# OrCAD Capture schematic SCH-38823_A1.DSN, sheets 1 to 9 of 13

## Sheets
1 Page11 BOOT_CFG: size C; title: X-8MNANOLPD4-CPU; rev: A; company: NXP Semiconductor; note: SCH-38823 PDF: SPF-38823; note: NO. 192 Liangjing Rd. Pudong New Area, ShangHai
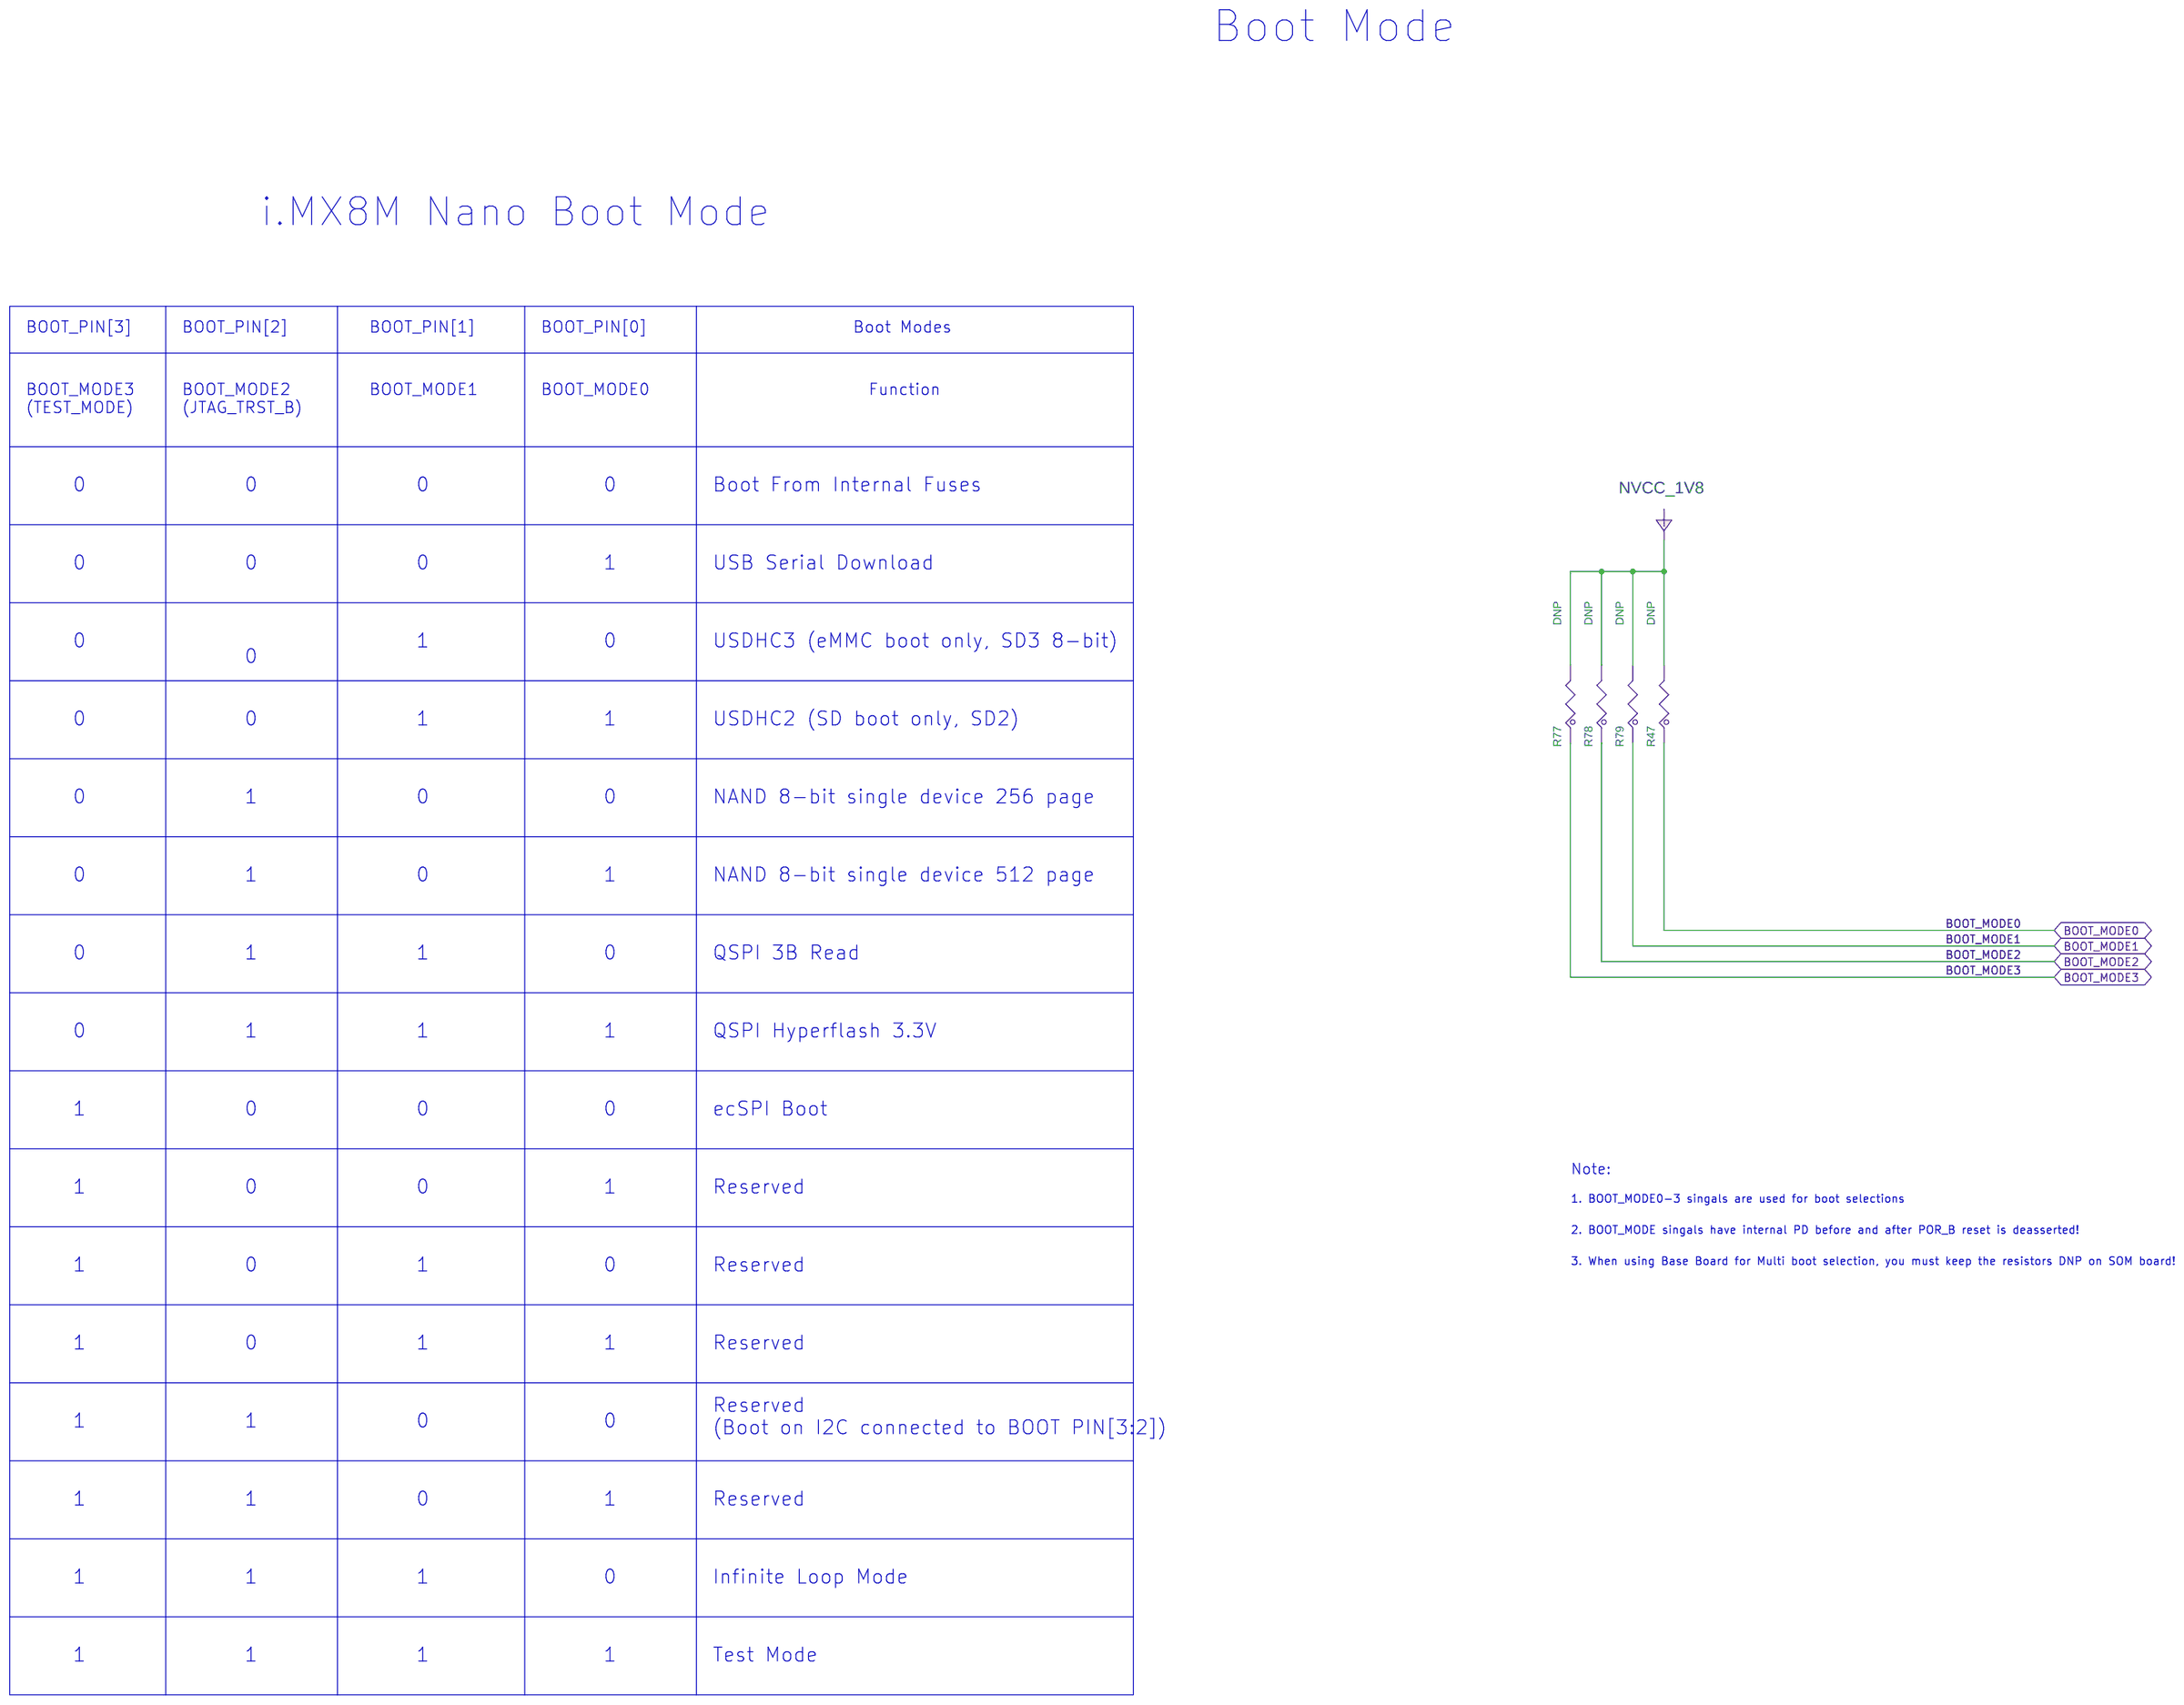
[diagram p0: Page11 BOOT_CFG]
2 Page01 COVER
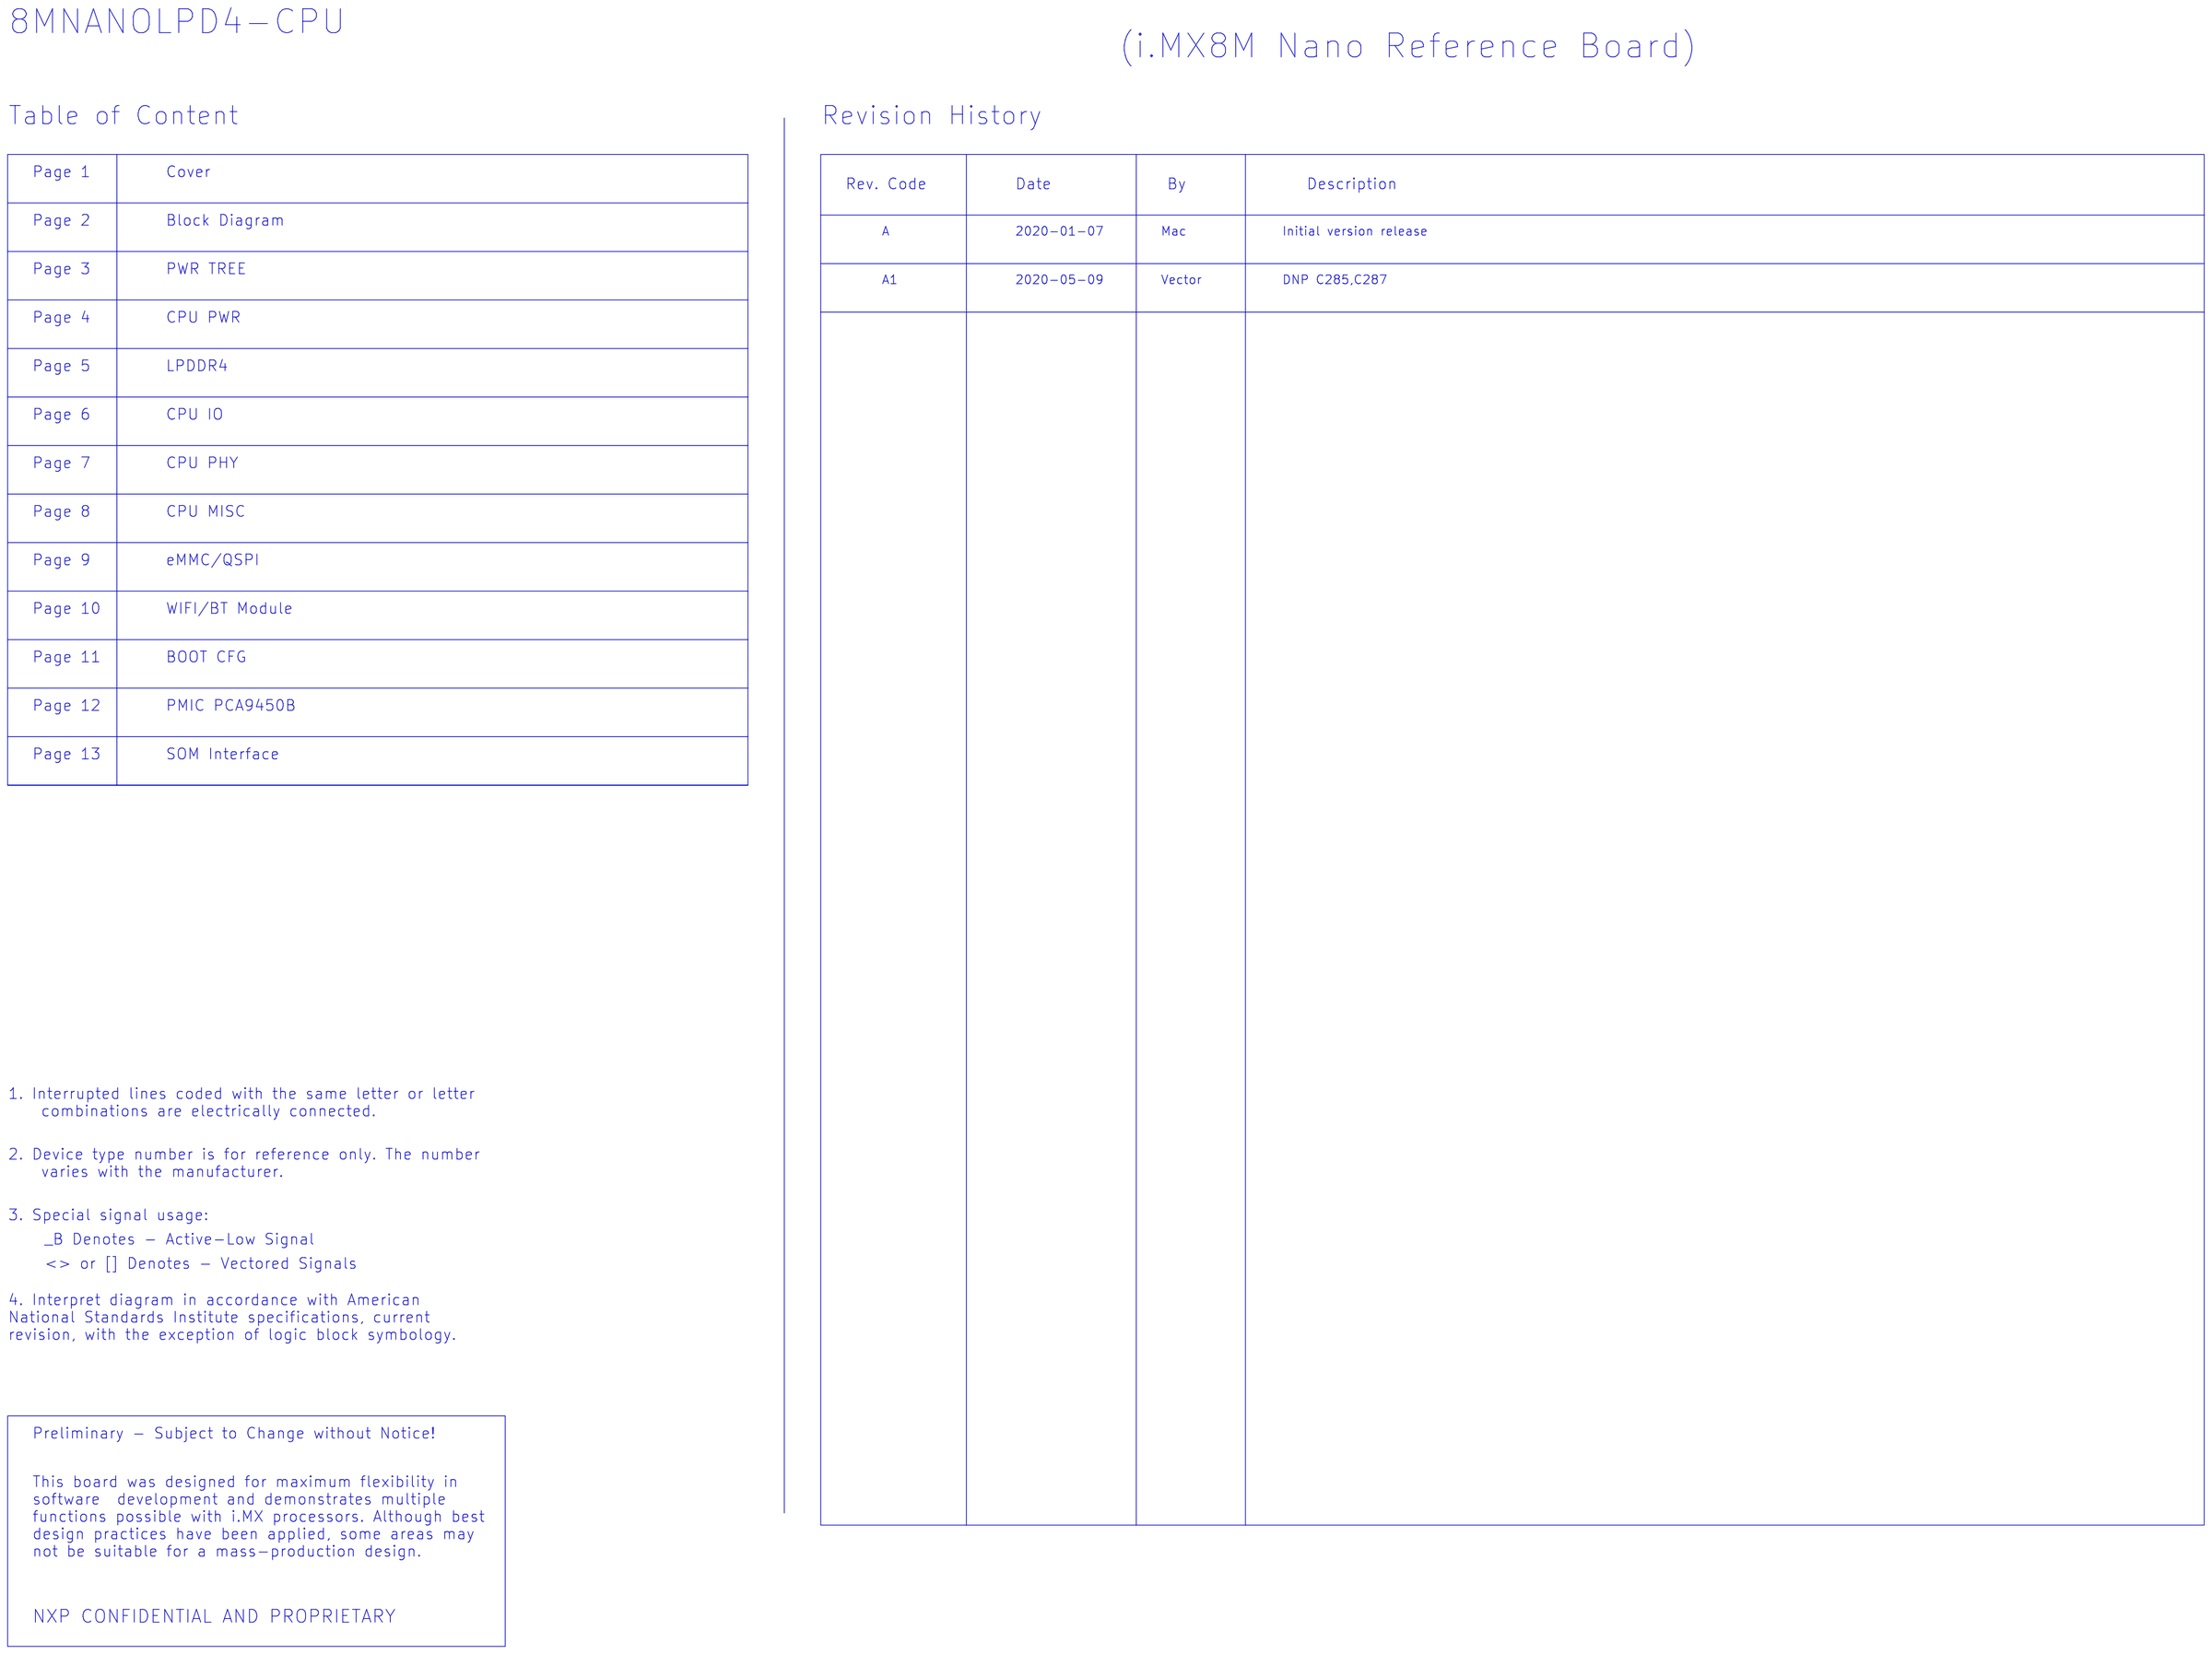
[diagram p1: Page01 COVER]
3 Page02 BLOCK DIAGRAM
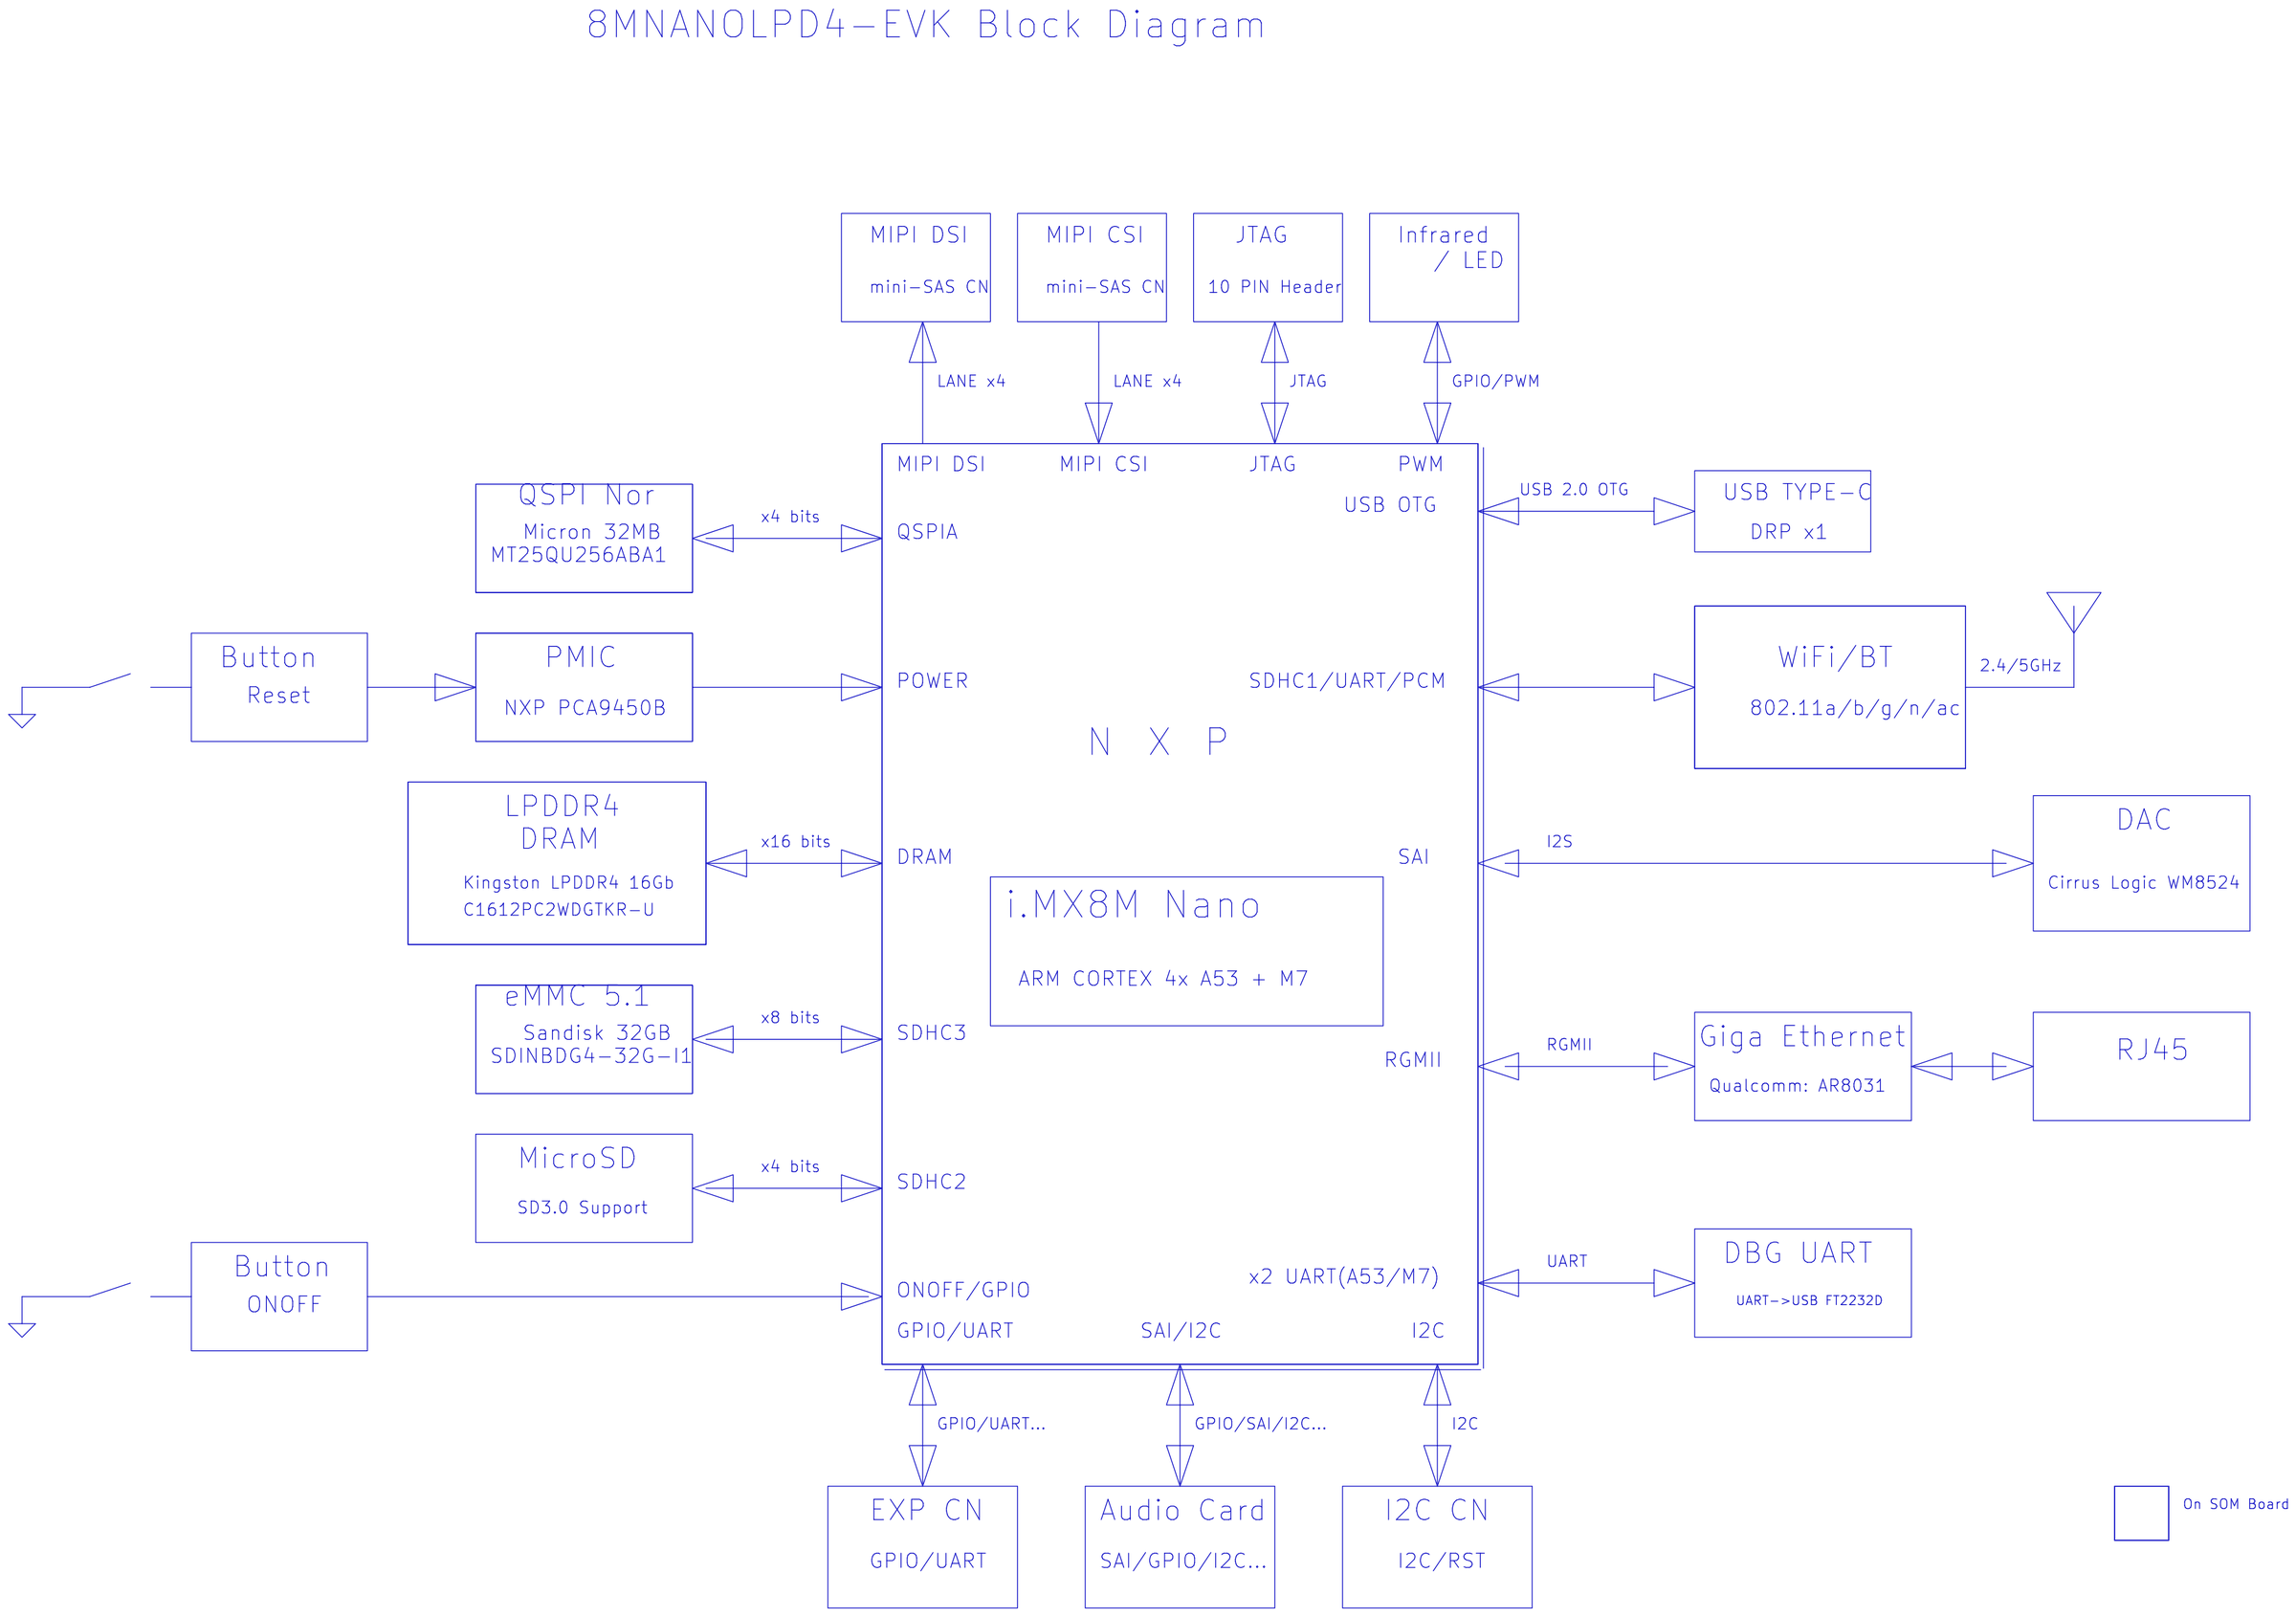
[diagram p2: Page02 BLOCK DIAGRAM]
4 Page03 PWR TREE
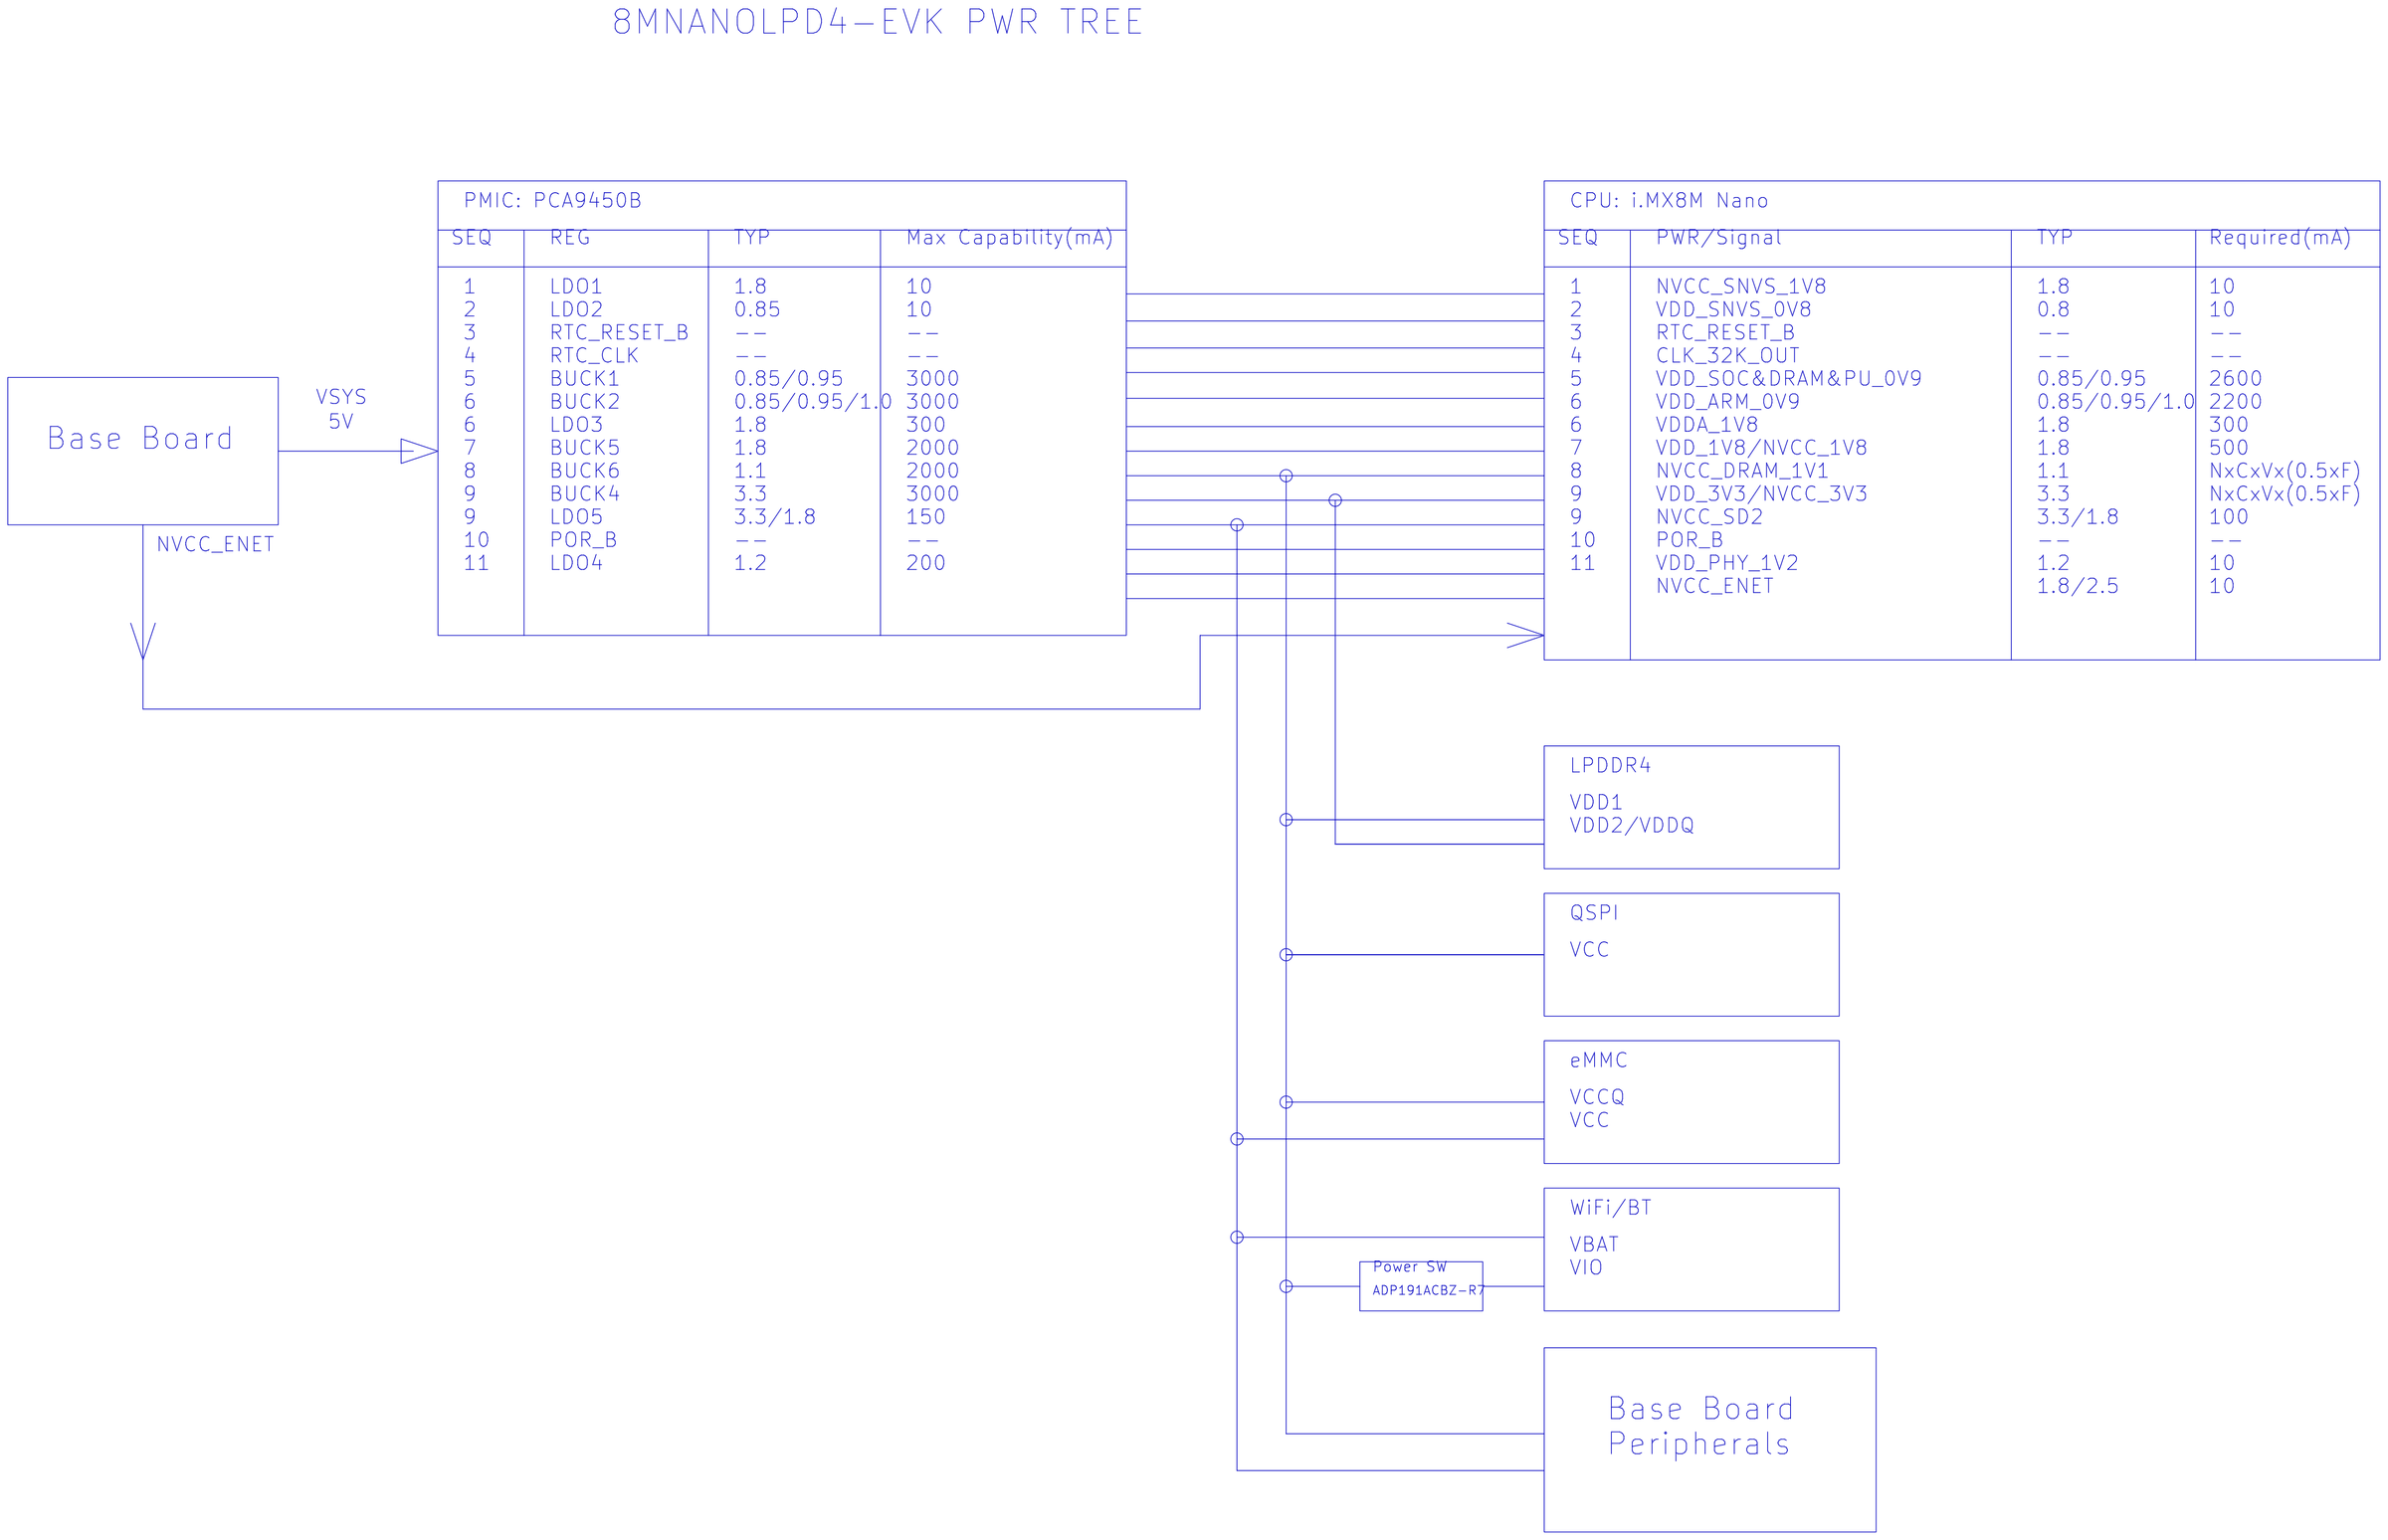
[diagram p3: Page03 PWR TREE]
5 Page04 CPU PWR: size C
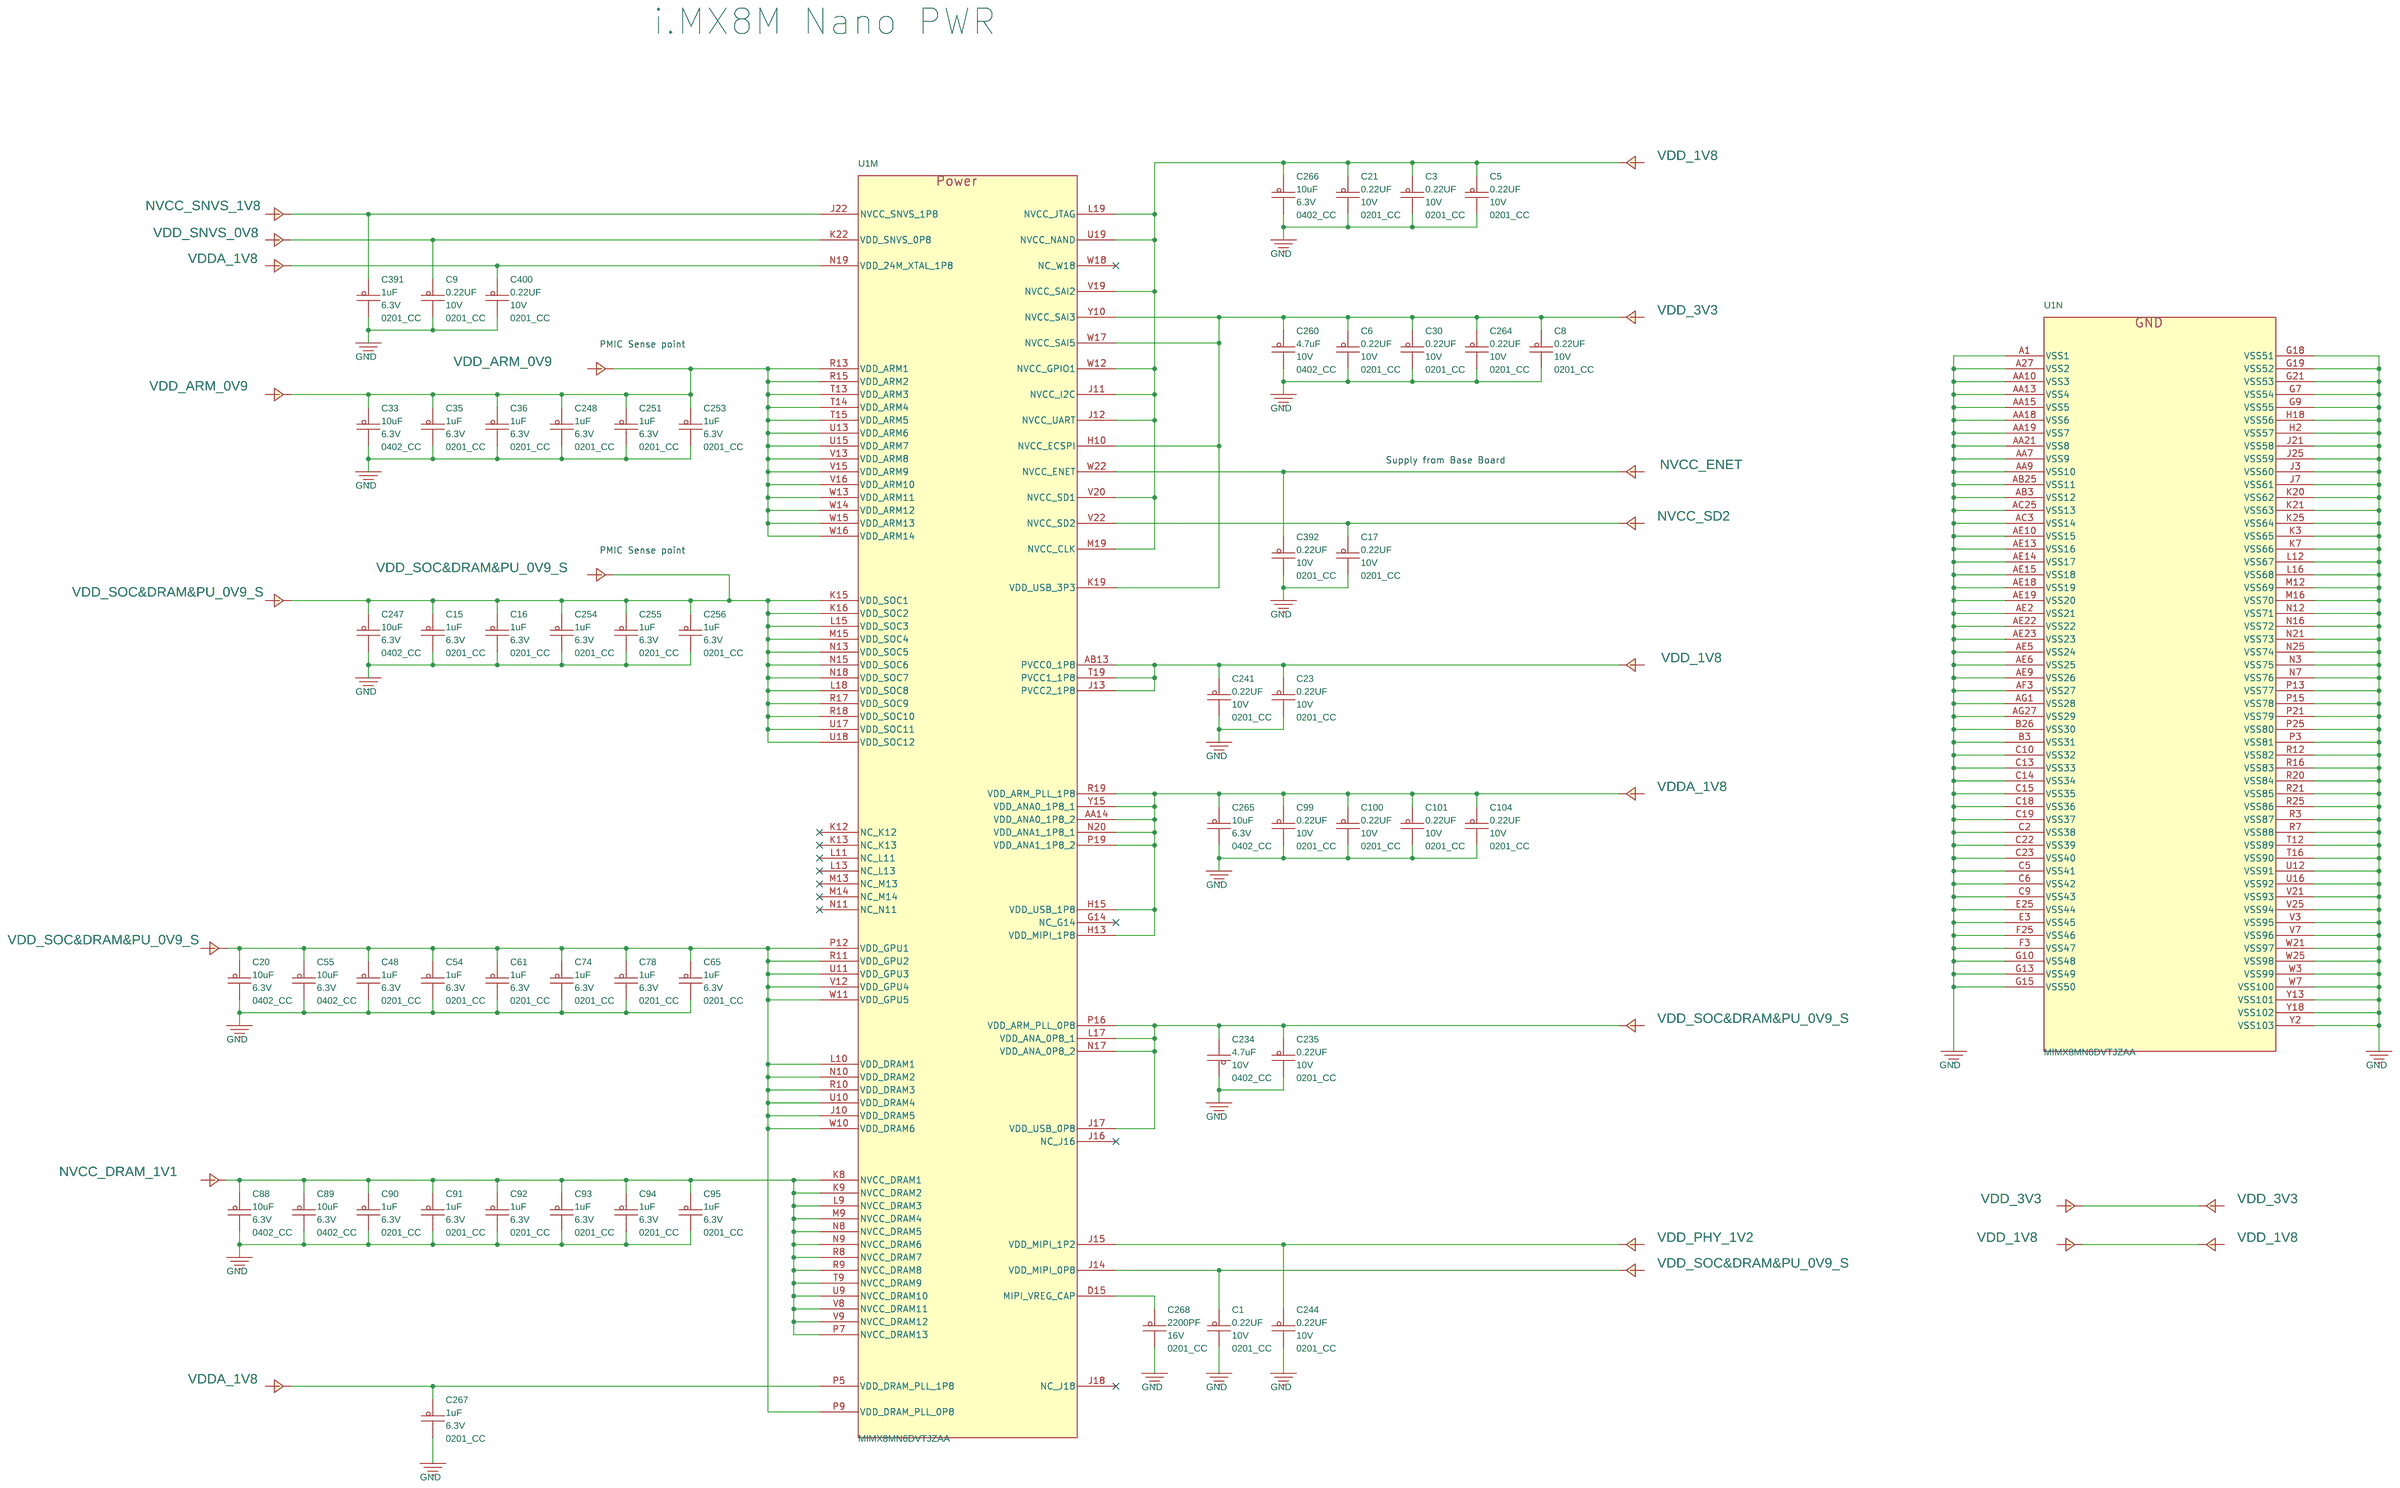
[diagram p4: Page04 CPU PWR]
6 Page05 LPDDR4: size C; title: X-8MNANOD4-CPU
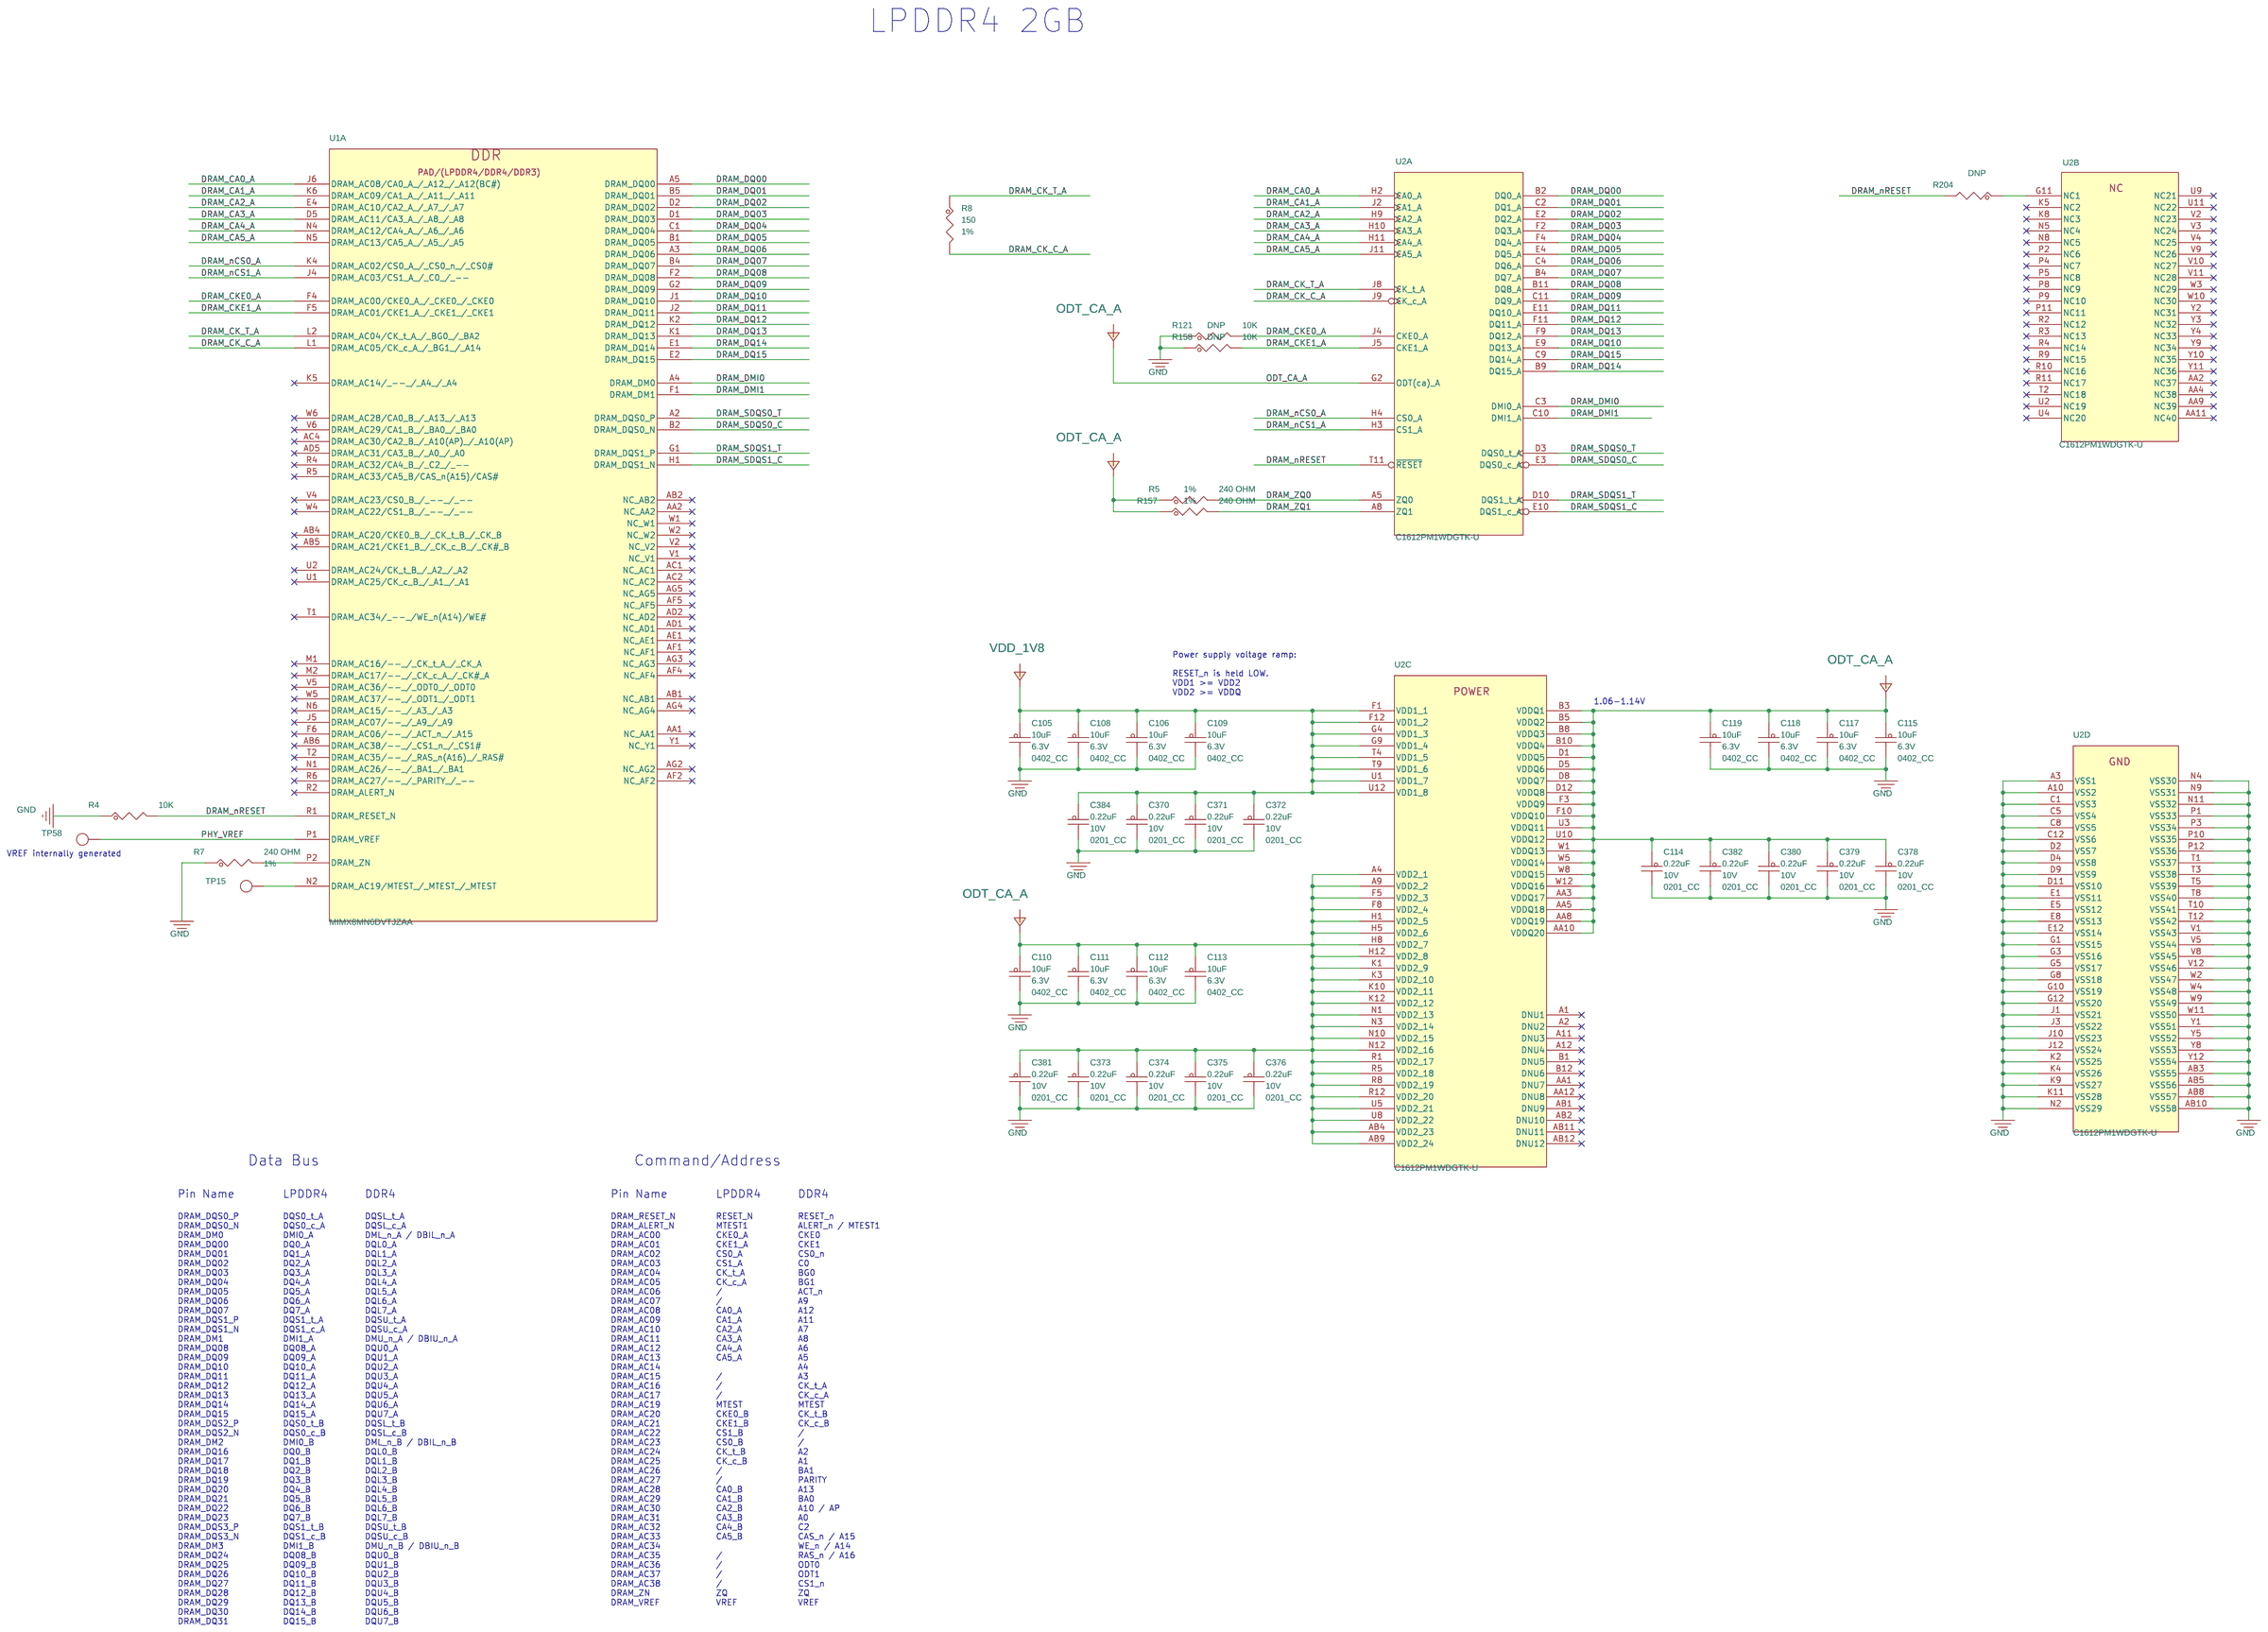
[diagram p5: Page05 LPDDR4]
7 Page06 CPU IO: size C; title: X-8MNANOD4-CPU
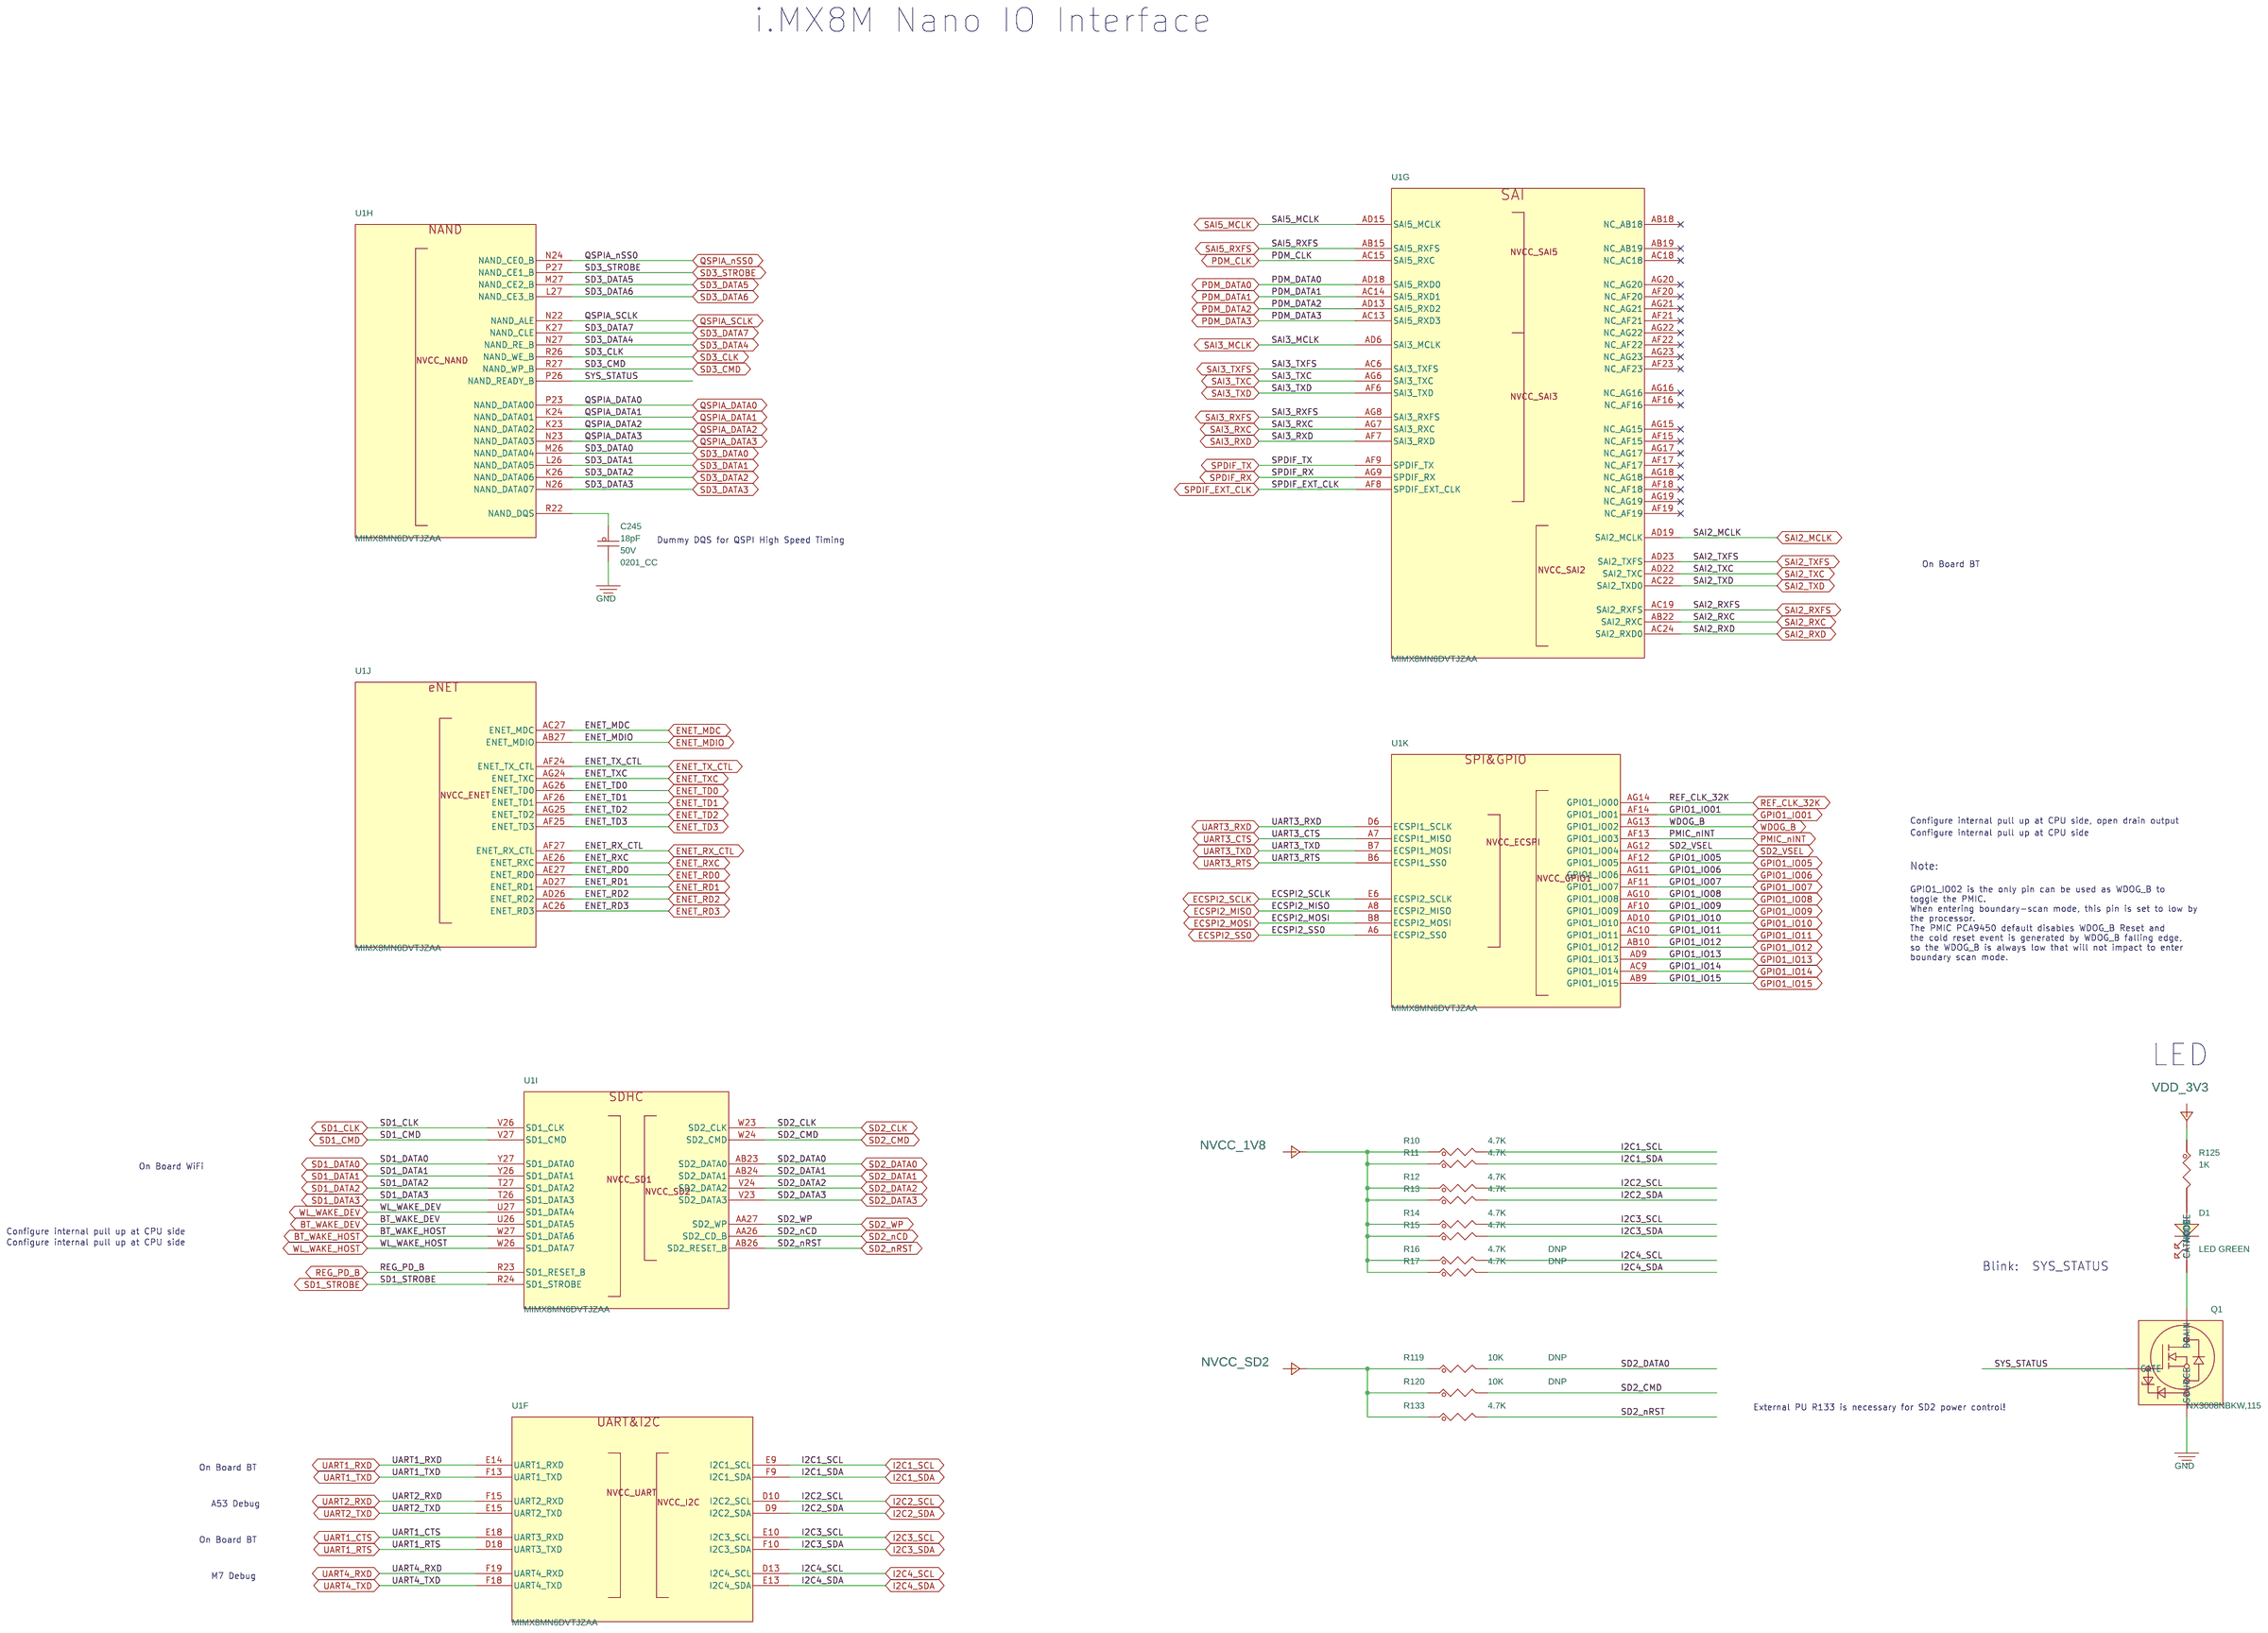
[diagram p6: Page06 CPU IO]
8 Page08 CPU MISC: size A4
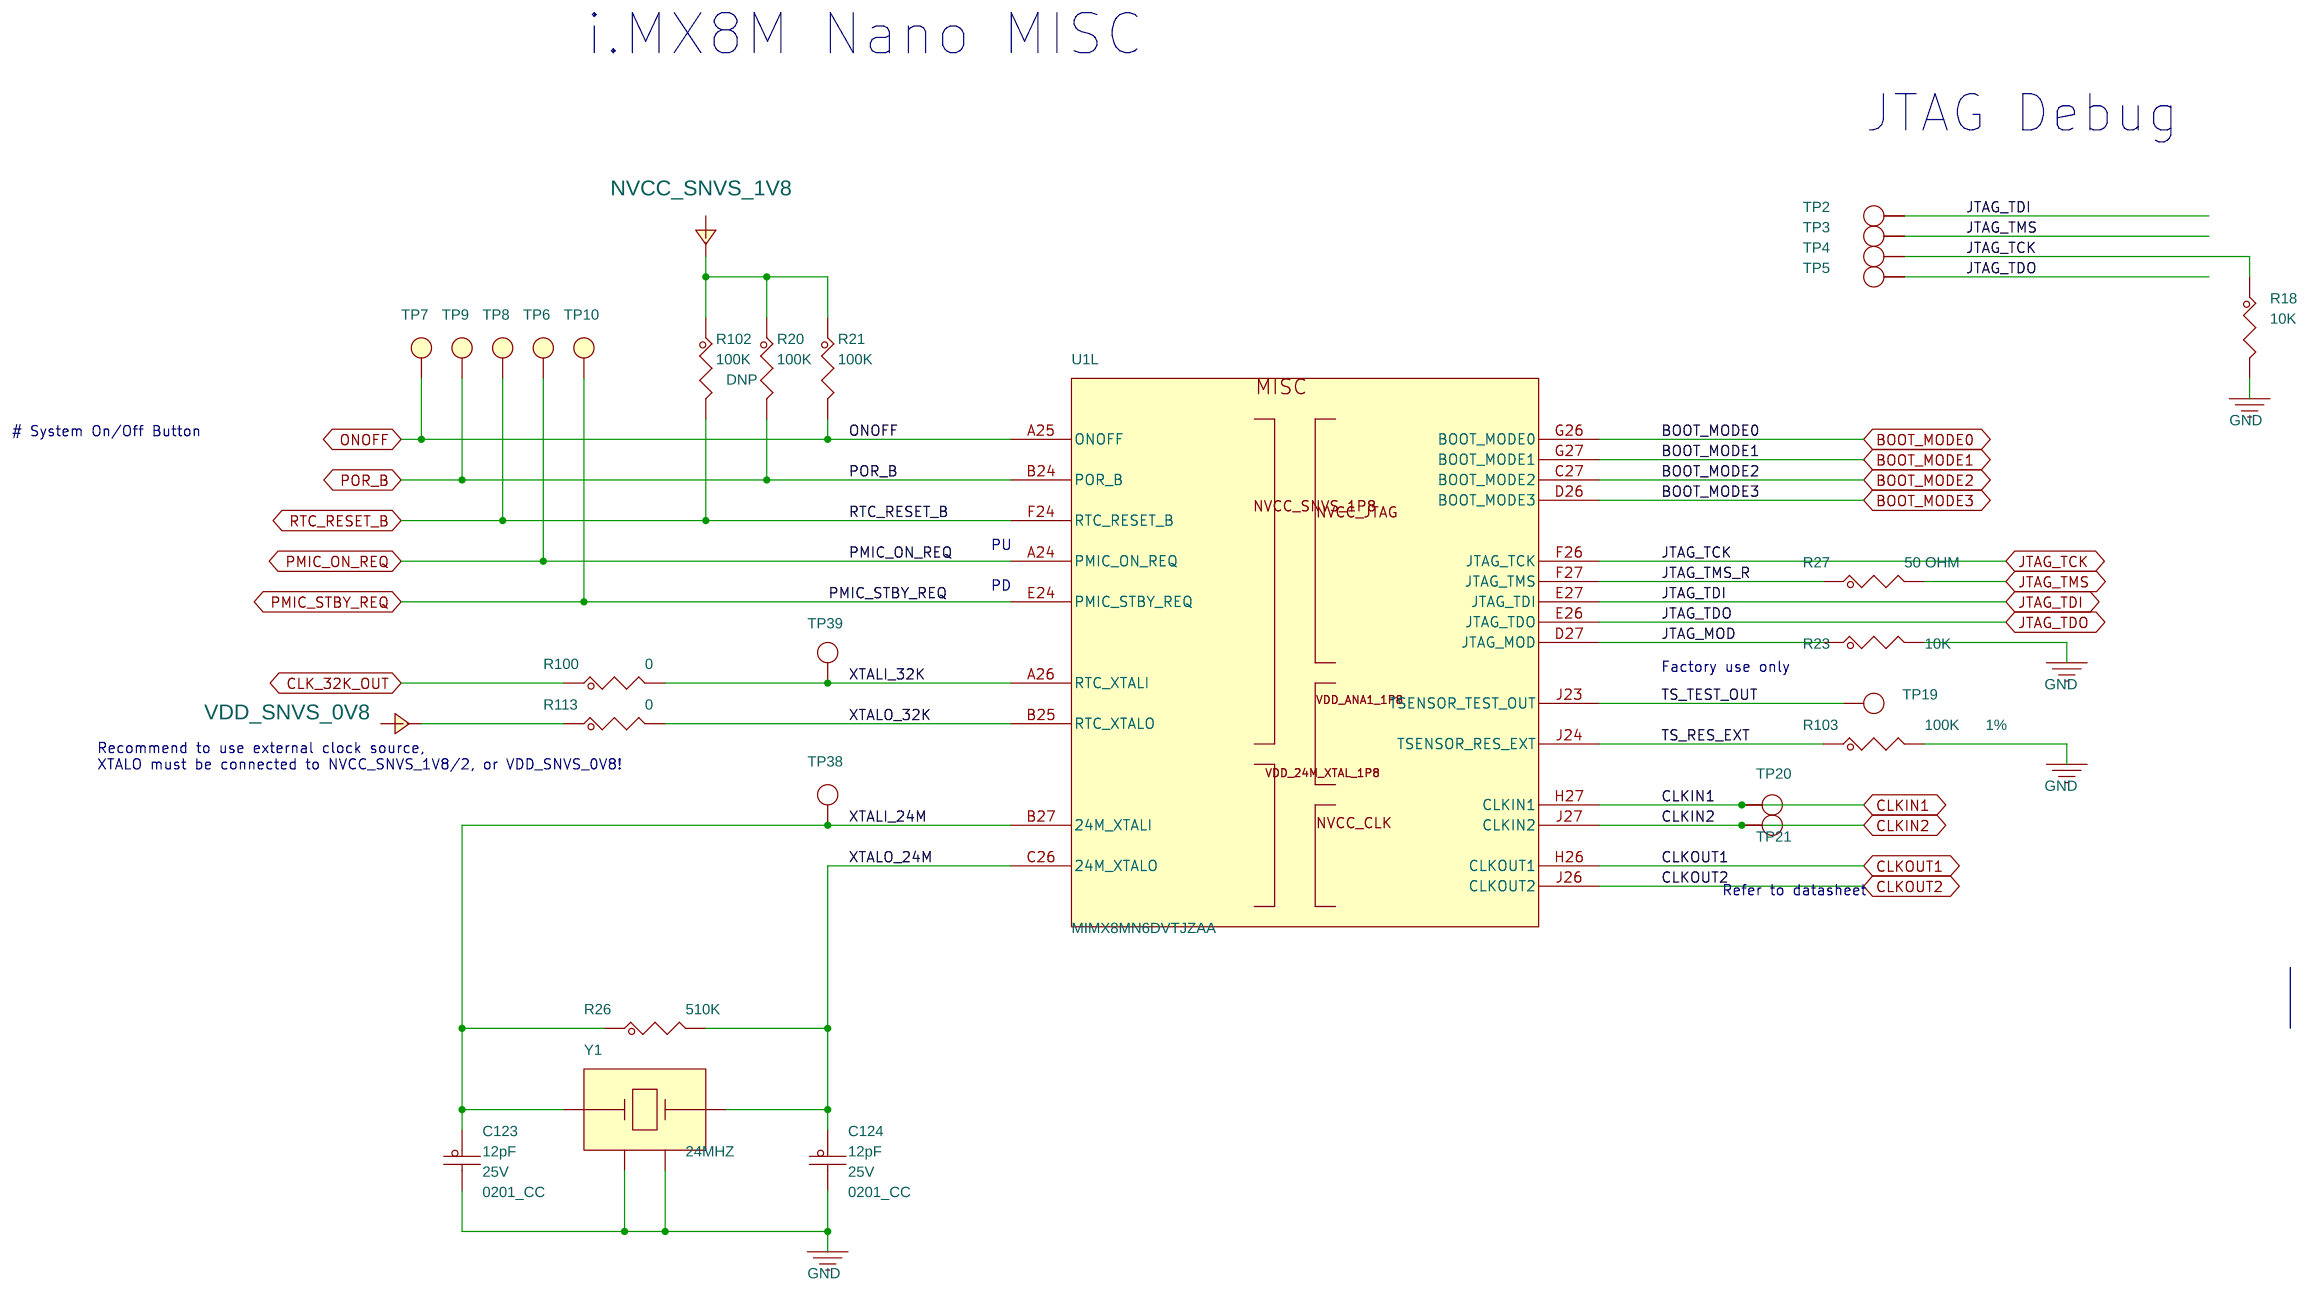
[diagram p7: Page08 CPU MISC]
9 Page07 CPU PHY: size B
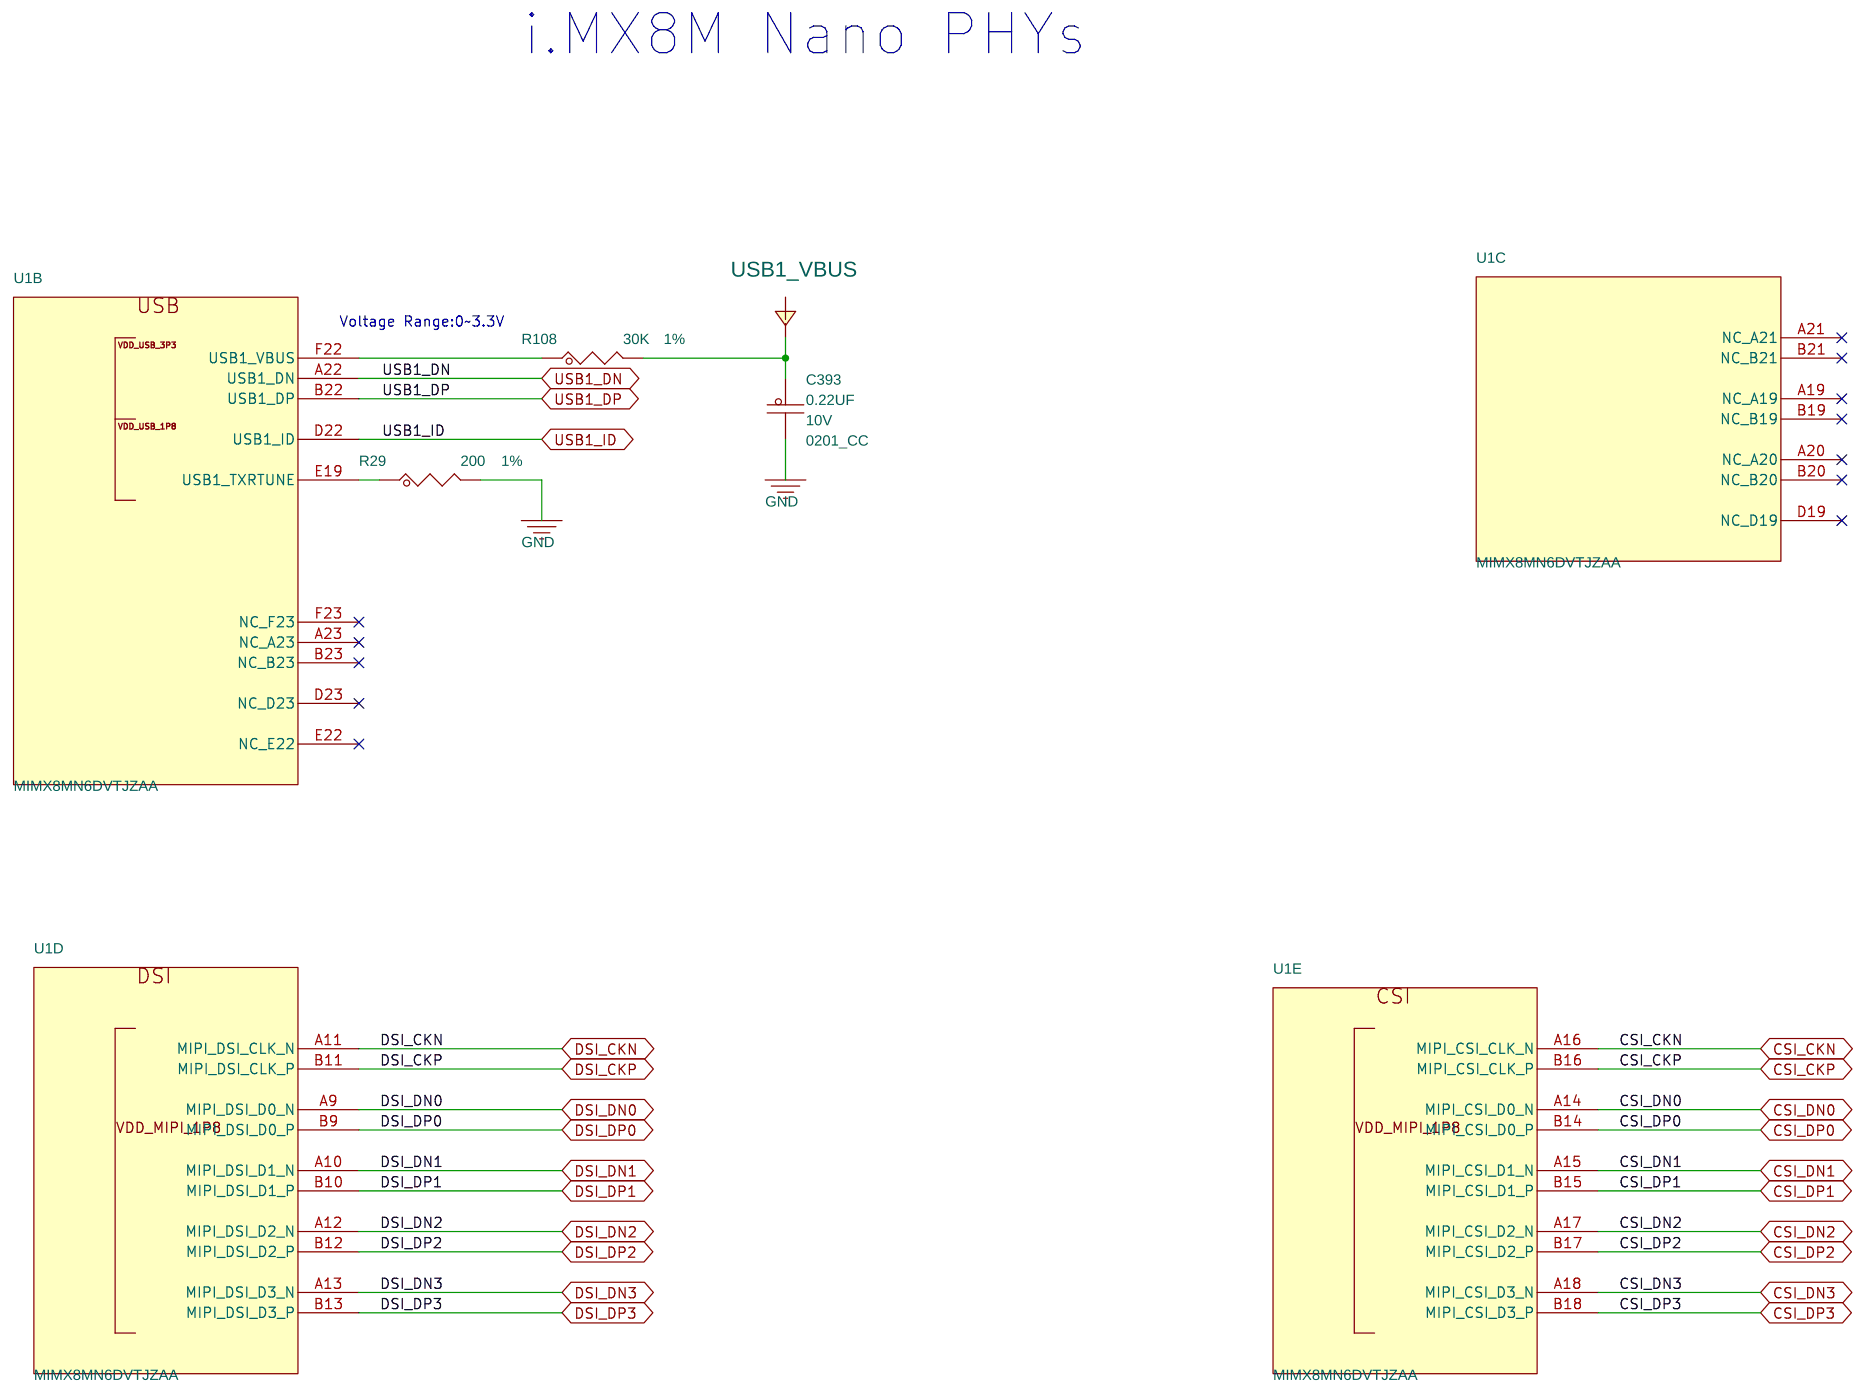
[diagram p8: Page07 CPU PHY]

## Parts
sheet Page04 CPU PWR
C1  0.22UF  [0201_CC]
C3  0.22UF  [0201_CC]
C5  0.22UF  [0201_CC]
C6  0.22UF  [0201_CC]
C8  0.22UF  [0201_CC]
C9  0.22UF  [0201_CC]
C15  1uF  [0201_CC]
C16  1uF  [0201_CC]
C17  0.22UF  [0201_CC]
C20  10uF  [0402_CC]
C21  0.22UF  [0201_CC]
C23  0.22UF  [0201_CC]
C30  0.22UF  [0201_CC]
C33  10uF  [0402_CC]
C35  1uF  [0201_CC]
C36  1uF  [0201_CC]
C48  1uF  [0201_CC]
C54  1uF  [0201_CC]
C55  10uF  [0402_CC]
C61  1uF  [0201_CC]
C65  1uF  [0201_CC]
C74  1uF  [0201_CC]
C78  1uF  [0201_CC]
C88  10uF  [0402_CC]
C89  10uF  [0402_CC]
C90  1uF  [0201_CC]
C91  1uF  [0201_CC]
C92  1uF  [0201_CC]
C93  1uF  [0201_CC]
C94  1uF  [0201_CC]
C95  1uF  [0201_CC]
C99  0.22UF  [0201_CC]
C100  0.22UF  [0201_CC]
C101  0.22UF  [0201_CC]
C104  0.22UF  [0201_CC]
C234  4.7uF  [0402_CC]
C235  0.22UF  [0201_CC]
C241  0.22UF  [0201_CC]
C244  0.22UF  [0201_CC]
C247  10uF  [0402_CC]
C248  1uF  [0201_CC]
C251  1uF  [0201_CC]
C253  1uF  [0201_CC]
C254  1uF  [0201_CC]
C255  1uF  [0201_CC]
C256  1uF  [0201_CC]
C260  4.7uF  [0402_CC]
C264  0.22UF  [0201_CC]
C265  10uF  [0402_CC]
C266  10uF  [0402_CC]
C267  1uF  [0201_CC]
C268  2200PF  [0201_CC]
C391  1uF  [0201_CC]
C392  0.22UF  [0201_CC]
C400  0.22UF  [0201_CC]
sheet Page05 LPDDR4
C105  10uF  [0402_CC]
C106  10uF  [0402_CC]
C108  10uF  [0402_CC]
C109  10uF  [0402_CC]
C110  10uF  [0402_CC]
C111  10uF  [0402_CC]
C112  10uF  [0402_CC]
C113  10uF  [0402_CC]
C114  0.22uF  [0201_CC]
C115  10uF  [0402_CC]
C117  10uF  [0402_CC]
C118  10uF  [0402_CC]
C119  10uF  [0402_CC]
C370  0.22uF  [0201_CC]
C371  0.22uF  [0201_CC]
C372  0.22uF  [0201_CC]
C373  0.22uF  [0201_CC]
C374  0.22uF  [0201_CC]
C375  0.22uF  [0201_CC]
C376  0.22uF  [0201_CC]
C378  0.22uF  [0201_CC]
C379  0.22uF  [0201_CC]
C380  0.22uF  [0201_CC]
C381  0.22uF  [0201_CC]
C382  0.22uF  [0201_CC]
C384  0.22uF  [0201_CC]
R4  10K  [0201_CC]
R5  240 OHM  [0201_CC]
R7  240 OHM  [0201_CC]
R8  150  [0402_CC]
R121  10K  [0201_CC]
R157  240 OHM  [0201_CC]
R158  10K  [0201_CC]
R204  0  [0402_CC]
TP15  TPAD_020  [tpad_020]
TP58  TPAD_020  [tpad_020]
U2  C1612PM1WDGTK-U  [bga200_0p65x0p8_10p1x14p6]  (sections A,B,C,D)
sheet Page06 CPU IO
C245  18pF  [0201_CC]
D1  LED GREEN  [LED_0603]
Q1  NX3008NBKW,115  [sc70_3]
R10  4.7K  [0201_CC]
R11  4.7K  [0201_CC]
R12  4.7K  [0201_CC]
R13  4.7K  [0201_CC]
R14  4.7K  [0201_CC]
R15  4.7K  [0201_CC]
R16  4.7K  [0201_CC]
R17  4.7K  [0201_CC]
R119  10K  [0201_CC]
R120  10K  [0201_CC]
R125  1K  [0201_CC]
R133  4.7K  [0201_CC]
sheet Page07 CPU PHY
C393  0.22UF  [0201_CC]
R29  200  [0201_CC]
R108  30K  [0201_CC]
sheet Page08 CPU MISC
C123  12pF  [0201_CC]
C124  12pF  [0201_CC]
R18  10K  [0201_CC]
R20  100K  [0201_CC]
R21  100K  [0201_CC]
R23  10K  [0201_CC]
R26  510K  [0402_CC]
R27  50 OHM  [0402_CC]
R100  0  [0402_CC]
R102  100K  [0201_CC]
R103  100K  [0201_CC]
R113  0  [0402_CC]
TP2  TPAD_020  [tpad_020]
TP3  TPAD_020  [tpad_020]
TP4  TPAD_020  [tpad_020]
TP5  TPAD_020  [tpad_020]
TP6  TP_35MIL  [testpoint_35mil]
TP7  TP_35MIL  [testpoint_35mil]
TP8  TP_35MIL  [testpoint_35mil]
TP9  TP_35MIL  [testpoint_35mil]
TP10  TP_35MIL  [testpoint_35mil]
TP19  TPAD_020  [tpad_020]
TP20  TPAD_020  [tpad_020]
TP21  TPAD_020  [tpad_020]
TP38  TPAD_020  [tpad_020]
TP39  TPAD_020  [tpad_020]
U1  MIMX8MN6DVTJZAA  [bga486_0p5_14x14]  (sections A,B,C,D,E,F,G,H,I,J,K,L,M,N)
Y1  24MHZ  [xtlosc4_3p2x2p5mm_sm]
sheet Page11 BOOT_CFG
R47  10K  [0402_CC]
R77  10K  [0402_CC]
R78  10K  [0402_CC]
R79  10K  [0402_CC]

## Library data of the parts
C1 C244 = CAP_NP: CAP CER 0.22UF 10V 20% X5R 0201; AGILE_PN: 150-78815; CAD_APPROVED: Yes; FPLIST: CC0201,CC0201_HD,0201_CC,CC_0201_CIR,0201_CC_012SM_NSP; HEIGHT: 0.33MM; MFG_NAME01: Taiyo Yuden; MFG_PN01: LMK063BJ224MP-F; ROHS: Yes; Tolerance: 20%; VOLTAGE: 10V
C3 C5 C6 C8 C9 C17 C21 C23 C99-C101 C104 C114 C235 C241 C264 C370-C376 C378-C382 C384 C392 C393 C400 = CAP_NP: CAP CER 0.22UF 10V 20% X5R 0201; AGILE_PN: 150-78815; CAD_APPROVED: Yes; FPLIST: CC0201,CC0201_HD,0201_CC; HEIGHT: 0.33MM; MFG_NAME01: Taiyo Yuden; MFG_PN01: LMK063BJ224MP-F; ROHS: Yes; Tolerance: 20%; VOLTAGE: 10V
C15 C16 C35 C36 C48 C54 C61 C65 C74 C78 C90-C95 C248 C251 C253-C256 C267 C391 = CAP_NP: CAP CER 1uF 6.3V 20% X5R 0201; AGILE_PN: 150-79407; CAD_APPROVED: Yes; FPLIST: CC0201,CC0201_HD,0201_CC,0201_CC_012SM_NSP; HEIGHT: 0.35MM; MFG_NAME01: AVX; MFG_PN01: 02016D105MAT2A; Package Size: 0201; Package Type: 7” reel; ROHS: Yes; Tolerance: 20%; VOLTAGE: 6.3V
C20 C33 C55 C88 C89 C105 C106 C108-C113 C115 C117-C119 C247 C265 C266 = CAP_NP: CAP CER 10UF 6.3V 20% X5R 0402; AGILE_PN: 150-79163; CAD_APPROVED: Yes; FPLIST: CC0402_25,CC0402_HD,0402_CC; HEIGHT: 0.65 MM; MFG_NAME01: SAMSUNG ELECTRO MECHANICS; MFG_PN01: CL05A106MQ5NUNC; ROHS: Yes; Tolerance: 20%; VOLTAGE: 6.3V
C30 = CAP_NP: CAP CER 0.22UF 10V 20% X5R 0201; AGILE_PN: 150-78815; CAD_APPROVED: Yes; FPLIST: CC0201,CC0201_HD,0201_CC,0201_CC_012SM_NSP; HEIGHT: 0.33MM; MFG_NAME01: Taiyo Yuden; MFG_PN01: LMK063BJ224MP-F; ROHS: Yes; Tolerance: 20%; VOLTAGE: 10V
C234 C260 = CAP_NP: CAP CER 4.7uF 10V 10% X5R 0402; AGILE_PN: 150-80044; CAD_APPROVED: Yes; FPLIST: CC0402_25,CC0402_HD,0402_CC; HEIGHT: 0.65MM; MFG_NAME01: Samsung Electro Mechanics; MFG_PN01: CL05A475KP5NRNC; ROHS: Yes; Tolerance: 10%; VOLTAGE: 10V
C268 = CAP_NP: CAP CER 2200PF 16V 10% X7R 0201; AGILE_PN: 150-78660; CAD_APPROVED: Yes; FPLIST: CC0201,CC0201_HD,0201_CC; HEIGHT: 0.33 MM; MFG_NAME01: MURATA; MFG_PN01: GRM033R71C222KA88D; ROHS: Yes; Tolerance: 20%; VOLTAGE: 16V
R4 R18 R23 = RES: RES MF 10K 1/20W 5% 0201; AGILE_PN: 470-79719; CAD_APPROVED: Yes; FPLIST: RC0201,0201_CC; HEIGHT: 0.26 MM; MFG_NAME01: RALEC ELECTRONIC CORP; MFG_PN01: RTT01103JTH; ROHS: Yes; Tolerance: 5%
R5 R7 R157 = RES: RES MF 240 OHM 1/20W 1% 0201; AGILE_PN: 470-81317; CAD_APPROVED: Yes; FPLIST: CC0201,CC0201_HD,0201_CC; HEIGHT: 0.26MM; MFG_NAME01: YAGEO AMERICA; MFG_PN01: RC0201FR-07240RL; ROHS: Yes; Temp Range: -55°C ~ 125°C; Temp_Range: -55°C ~ 125°C; Tolerance: 1%; VOLTAGE: 25V
R8 = RES: RES MF 150 OHM 1/16W 1% 0402; AGILE_PN: 470-75353; CAD_APPROVED: Yes; FPLIST: RC0402_25,RC0402_HD,0402_CC; HEIGHT: 0.4MM; MFG_NAME01: NIC COMPONENTS CORP; MFG_PN01: NRCL04F1500TRF; ROHS: Yes; Tolerance: 1%
R119-R121 R158 = RES: RES MF 10K 1/20W 5% 0201; AGILE_PN: 470-79719; ASSY_OPT: DNP; CAD_APPROVED: Yes; FPLIST: RC0201,0201_CC; HEIGHT: 0.26 MM; MFG_NAME01: RALEC ELECTRONIC CORP; MFG_PN01: RTT01103JTH; ROHS: Yes; Tolerance: 5%
R204 = RES: RES MF ZERO OHM 1/16W 5% 0402; AGILE_PN: 470-75394; ASSY_OPT: DNP; CAD_APPROVED: Yes; FPLIST: RC0402_25,RC0402_HD,RC0402_X2,0402_CC; HEIGHT: 0.45 MM; MFG_NAME01: YAGEO AMERICA; MFG_PN01: RC0402JR-070RL; ROHS: Yes; SIGNAL_MODEL: DEFAULT_RESISTOR_10000OHM_2_1; TOL: 1%; Tolerance: 5%; VOLTAGE: 1/16W
TP2-TP5 TP15 TP19-TP21 TP38 TP39 TP58 = TESTLOOP: TEST POINT PAD 0.5MM DIA SMT, NO PART TO ORDER; AGILE_PN: 211-77484; ASSY_OPT: DNP; CAD_APPROVED: Yes; HEIGHT: 0.1MM; ROHS: Yes
U2 = C1612PC2WDGTKR-U_BGA200P: IC MEM LPDDR4 SDRAM 1024 Meg x 16 1.1V FBGA200; AGILE_PN: TMP-WF-36533; CAD_APPROVED: Yes; HEIGHT: 1.0MM; MFG_NAME01: KINGSTON TECHNOLOGY CORP; PRE_APN: 334-77858; ROHS: Yes; Temp Range: -10C to +85C; Temp_Range: -10C to +85C; VOLTAGE: 1.1V
C245 = CAP_NP: CAP CER 18pF 50V 5% C0G 0201; AGILE_PN: 150-79476; CAD_APPROVED: Yes; FPLIST: CC0201,CC0201_HD,0201_CC; HEIGHT: 0.33MM; MFG_NAME01: MURATA; MFG_PN01: GRM0335C1H180JA01D; Package Size: 0201; Package Type: &#966;180mm Paper taping; ROHS: Yes; Tolerance: 5%; VOLTAGE: 50V
D1 = LED: LED GRN SGL 25MA SMT 0603; AGILE_PN: 370-76672; CAD_APPROVED: Yes; HEIGHT: 0.8 MM; MFG_NAME01: DIALIGHT; MFG_PN01: 598-8070-107F; ROHS: Yes; VOLTAGE: 2V
Q1 = NMOS_NX3008NBK: TRAN NMOS SW 30V 350mA AEC-Q101 SC-70; AGILE_PN: 480-79736; CAD_APPROVED: Yes; HEIGHT: 1.1MM; MFG_NAME01: NEXPERIA; ROHS: Yes
R10-R15 R133 = RES: RES MF 4.7K 1/20W 5% AEC-Q200 0201; AGILE_PN: 470-79700; CAD_APPROVED: Yes; FPLIST: RC0201,0201_CC; HEIGHT: 0.25MM; MFG_NAME01: KOA SPEER; MFG_PN01: RK73B1HTTC472J; ROHS: Yes; Temp Range: -55C to +155C; Temp_Range: -55C to +155C; Tolerance: 5%
R16 R17 = RES: RES MF 4.7K 1/20W 5% AEC-Q200 0201; AGILE_PN: 470-79700; ASSY_OPT: DNP; CAD_APPROVED: Yes; FPLIST: RC0201,0201_CC; HEIGHT: 0.25MM; MFG_NAME01: KOA SPEER; MFG_PN01: RK73B1HTTC472J; ROHS: Yes; Temp Range: -55C to +155C; Temp_Range: -55C to +155C; Tolerance: 5%
R125 = RES: RES MF 1.0K OHM 1/20W 1% 30V -55+155C 0201; AGILE_PN: 470-82221; CAD_APPROVED: Yes; FPLIST: RC0201,0201_CC; HEIGHT: 0.28MM; MFG_NAME01: VISHAY INTERTECHNOLOGY; MFG_PN01: CRCW02011K00FNED; ROHS: Yes; Temp Range: -55°C ~ 155°C; Temp_Range: -55°C ~ 155°C; Tolerance: 1%; VOLTAGE: 30
R29 = RES: RES MF 200 OHM 1/20W 1% 0201; AGILE_PN: 470-82323; CAD_APPROVED: Yes; FPLIST: RC0201,0201_CC; HEIGHT: 0.26MM; MFG_NAME01: YAGEO AMERICA; MFG_PN01: RC0201FR-07200RL; ROHS: Yes; Temp Range: -55°C ~ 125°C; Temp_Range: -55°C ~ 125°C; Tolerance: 1%; VOLTAGE: 25V
R108 = RES: RES MF 30K 1/20W 1% 0201; AGILE_PN: 470-81353; CAD_APPROVED: Yes; FPLIST: RC0201,0201_CC; HEIGHT: 0.26MM; MFG_NAME01: YAGEO AMERICA; MFG_PN01: RC0201FR-0730KL; ROHS: Yes; Temp Range: -55°C ~ 155°C; Temp_Range: -55°C ~ 155°C; Tolerance: 1%; VOLTAGE: 25V
C123 C124 = CAP_NP: CAP CER 12PF 25V 5% C0G AEC-Q200 0201; AGILE_PN: 150-79813; CAD_APPROVED: Yes; FPLIST: CC0201,CC0201_HD,0201_CC; HEIGHT: 0.33MM; MFG_NAME01: TDK; MFG_PN01: CGA1A2C0G1E120J030BA; ROHS: Yes; Tolerance: 5%; VOLTAGE: 25V
R20 R21 R103 = RES: RES MF 100K 1/20W 1% 0201; AGILE_PN: 470-77704; CAD_APPROVED: Yes; FPLIST: RC0201,0201_CC; HEIGHT: 0.26MM; MFG_NAME01: SKYMOS; MFG_PN01: RC-0201-104FT; ROHS: Yes; Tolerance: 1%
R26 = RES: RES MF 510K 1/16W 5% 0402; AGILE_PN: 470-76166; CAD_APPROVED: Yes; FPLIST: RC0402_25,RC0402_HD,0402_CC; HEIGHT: 0.4 MM; MFG_NAME01: PANASONIC; MFG_PN01: ERJ-2GEJ514X; ROHS: Yes; Tolerance: 5%
R27 = RES: RES MF 50 OHM 1/20W 5% 0402; AGILE_PN: 470-82494; CAD_APPROVED: YES; FPLIST: RC0402_25,RC0402_HD,0402_CC; HEIGHT: 0.627MM; MFG_NAME01: VISHAY; MFG_PN01: CH0402-50RJNPA; Package Size: 0402 (1005 Metric); ROHS: Yes; Tolerance: 5%
R100 R113 = RES: RES MF ZERO OHM 1/16W 5% 0402; AGILE_PN: 470-75394; CAD_APPROVED: Yes; FPLIST: RC0402_25,RC0402_HD,RC0402_X2,0402_CC; HEIGHT: 0.45 MM; MFG_NAME01: YAGEO AMERICA; MFG_PN01: RC0402JR-070RL; ROHS: Yes; Tolerance: 5%; VOLTAGE: 1/16W
R102 = RES: RES MF 100K 1/20W 1% 0201; AGILE_PN: 470-77704; ASSY_OPT: DNP; CAD_APPROVED: Yes; FPLIST: RC0201,0201_CC; HEIGHT: 0.26MM; MFG_NAME01: SKYMOS; MFG_PN01: RC-0201-104FT; ROHS: Yes; Tolerance: 1%
TP6-TP10 = T_POINT_R: TEST POINT PAD .035 SMT, no part to order; AGILE_PN: 510-75618; ASSY_OPT: DNP; CAD_APPROVED: Yes; HEIGHT: 0.1MM; ROHS: Yes
U1 = MIMX8NN_BGA486P: IC CPU QUAD CORTEX A53+M7 1.5GHZ BGA486; AGILE_PN: TMP-WF-35485; CAD_APPROVED: Yes; HEIGHT: 1.25MM; MFG_NAME01: NXP SEMICONDUCTORS; PRE_APN: 330-77106; ROHS: Yes; Temp Range: 0°C to 95°C; Temp_Range: 0°C to 95°C
Y1 = XTAL_13: XTAL 24MHZ 9pF -- SMT 3.2X2.5MM; AGILE_PN: 230-77392; CAD_APPROVED: Yes; HEIGHT: 0.60MM; MFG_NAME01: EPSON TOYOCOM CORPORATION; MFG_PN01: TSX-3225 24.0000MF15X-AC3; ROHS: Yes
R47 R77-R79 = RES: RES MF 10K 1/16W 5% 0402; AGILE_PN: 470-75557; ASSY_OPT: DNP; CAD_APPROVED: Yes; FPLIST: RC0402_25,RC0402_HD,0402_CC; HEIGHT: 0.4 MM; MFG_NAME01: VISHAY INTERTECHNOLOGY; MFG_PN01: CRCW040210K0JNED; ROHS: Yes; TOL: 5%; Tolerance: 5%

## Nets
GND: C1.2 C3.2 C5.2 C6.2 C8.2 C9.2 C15.2 C16.2 C17.2 C20.2 C21.2 C23.2 C30.2 C33.2 C35.2 C36.2 C48.2 C54.2 C55.2 C61.2 C65.2 C74.2 C78.2 C88.2 C89.2 C90.2 C91.2 C92.2 C93.2 C94.2 C95.2 C99.2 C100.2 C101.2 C104.2 C105.2 C106.2 C108.2 C109.2 C110.2 C111.2 C112.2 C113.2 C114.2 C115.2 C117.2 C118.2 C119.2 C123.2 C124.2 C234.1 C235.2 C241.2 C244.2 C245.2 C247.2 C248.2 C251.2 C253.2 C254.2 C255.2 C256.2 C260.2 C264.2 C265.2 C266.2 C267.2 C268.2 C370.2 C371.2 C372.2 C373.2 C374.2 C375.2 C376.2 C378.2 C379.2 C380.2 C381.2 C382.2 C384.2 C391.2 C392.2 C393.2 C400.2 Q1.2(SOURCE) R4.1 R7.1 R18.2 R23.2 R29.2 R103.2 R121.1 R158.1 U1.A1(VSS1) U1.A27(VSS2) U1.AA7(VSS9) U1.AA9(VSS10) U1.AA10(VSS3) U1.AA13(VSS4) U1.AA15(VSS5) U1.AA18(VSS6) U1.AA19(VSS7) U1.AA21(VSS8) U1.AB3(VSS12) U1.AB25(VSS11) U1.AC3(VSS14) U1.AC25(VSS13) U1.AE2(VSS21) U1.AE5(VSS24) U1.AE6(VSS25) U1.AE9(VSS26) U1.AE10(VSS15) U1.AE13(VSS16) U1.AE14(VSS17) U1.AE15(VSS18) U1.AE18(VSS19) U1.AE19(VSS20) U1.AE22(VSS22) U1.AE23(VSS23) U1.AF3(VSS27) U1.AG1(VSS28) U1.AG27(VSS29) U1.B3(VSS31) U1.B26(VSS30) U1.C2(VSS38) U1.C5(VSS41) U1.C6(VSS42) U1.C9(VSS43) U1.C10(VSS32) U1.C13(VSS33) U1.C14(VSS34) U1.C15(VSS35) U1.C18(VSS36) U1.C19(VSS37) U1.C22(VSS39) U1.C23(VSS40) U1.E3(VSS45) U1.E25(VSS44) U1.F3(VSS47) U1.F25(VSS46) U1.G7(VSS54) U1.G9(VSS55) U1.G10(VSS48) U1.G13(VSS49) U1.G15(VSS50) U1.G18(VSS51) U1.G19(VSS52) U1.G21(VSS53) U1.H2(VSS57) U1.H18(VSS56) U1.J3(VSS60) U1.J7(VSS61) U1.J21(VSS58) U1.J25(VSS59) U1.K3(VSS65) U1.K7(VSS66) U1.K20(VSS62) U1.K21(VSS63) U1.K25(VSS64) U1.L12(VSS67) U1.L16(VSS68) U1.M12(VSS69) U1.M16(VSS70) U1.N3(VSS75) U1.N7(VSS76) U1.N12(VSS71) U1.N16(VSS72) U1.N21(VSS73) U1.N25(VSS74) U1.P3(VSS81) U1.P13(VSS77) U1.P15(VSS78) U1.P21(VSS79) U1.P25(VSS80) U1.R3(VSS87) U1.R7(VSS88) U1.R12(VSS82) U1.R16(VSS83) U1.R20(VSS84) U1.R21(VSS85) U1.R25(VSS86) U1.T12(VSS89) U1.T16(VSS90) U1.U12(VSS91) U1.U16(VSS92) U1.V3(VSS95) U1.V7(VSS96) U1.V21(VSS93) U1.V25(VSS94) U1.W3(VSS99) U1.W7(VSS100) U1.W21(VSS97) U1.W25(VSS98) U1.Y2(VSS103) U1.Y13(VSS101) U1.Y18(VSS102) U2.A3(VSS1) U2.A10(VSS2) U2.AB3(VSS55) U2.AB5(VSS56) U2.AB8(VSS57) U2.AB10(VSS58) U2.C1(VSS3) U2.C5(VSS4) U2.C8(VSS5) U2.C12(VSS6) U2.D2(VSS7) U2.D4(VSS8) U2.D9(VSS9) U2.D11(VSS10) U2.E1(VSS11) U2.E5(VSS12) U2.E8(VSS13) U2.E12(VSS14) U2.G1(VSS15) U2.G3(VSS16) U2.G5(VSS17) U2.G8(VSS18) U2.G10(VSS19) U2.G12(VSS20) U2.J1(VSS21) U2.J3(VSS22) U2.J10(VSS23) U2.J12(VSS24) U2.K2(VSS25) U2.K4(VSS26) U2.K9(VSS27) U2.K11(VSS28) U2.N2(VSS29) U2.N4(VSS30) U2.N9(VSS31) U2.N11(VSS32) U2.P1(VSS33) U2.P3(VSS34) U2.P10(VSS35) U2.P12(VSS36) U2.T1(VSS37) U2.T3(VSS38) U2.T5(VSS39) U2.T8(VSS40) U2.T10(VSS41) U2.T12(VSS42) U2.V1(VSS43) U2.V5(VSS44) U2.V8(VSS45) U2.V12(VSS46) U2.W2(VSS47) U2.W4(VSS48) U2.W9(VSS49) U2.W11(VSS50) U2.Y1(VSS51) U2.Y5(VSS52) U2.Y8(VSS53) U2.Y12(VSS54) Y1.2 Y1.4 ; also on sheet 10 11 12 13
VDD_ARM_0V9: C33.1 C35.1 C36.1 C248.1 C251.1 C253.1 U1.R13(VDD_ARM1) U1.R15(VDD_ARM2) U1.T13(VDD_ARM3) U1.T14(VDD_ARM4) U1.T15(VDD_ARM5) U1.U13(VDD_ARM6) U1.U15(VDD_ARM7) U1.V13(VDD_ARM8) U1.V15(VDD_ARM9) U1.V16(VDD_ARM10) U1.W13(VDD_ARM11) U1.W14(VDD_ARM12) U1.W15(VDD_ARM13) U1.W16(VDD_ARM14) ; also on sheet 12
VDD_PHY_1V2: C244.1 U1.J15(VDD_MIPI_1P2) ; also on sheet 12
VDD_SNVS_0V8: C9.1 R113.1 U1.K22(VDD_SNVS_0P8) ; also on sheet 12
VDD_SOC&DRAM&PU_0V9: C1.1 C15.1 C16.1 C20.1 C48.1 C54.1 C55.1 C61.1 C65.1 C74.1 C78.1 C234.2 C235.1 C247.1 C254.1 C255.1 C256.1 U1.J10(VDD_DRAM5) U1.J14(VDD_MIPI_0P8) U1.J17(VDD_USB_0P8) U1.K15(VDD_SOC1) U1.K16(VDD_SOC2) U1.L10(VDD_DRAM1) U1.L15(VDD_SOC3) U1.L17(VDD_ANA_0P8_1) U1.L18(VDD_SOC8) U1.M15(VDD_SOC4) U1.N10(VDD_DRAM2) U1.N13(VDD_SOC5) U1.N15(VDD_SOC6) U1.N17(VDD_ANA_0P8_2) U1.N18(VDD_SOC7) U1.P9(VDD_DRAM_PLL_0P8) U1.P12(VDD_GPU1) U1.P16(VDD_ARM_PLL_0P8) U1.R10(VDD_DRAM3) U1.R11(VDD_GPU2) U1.R17(VDD_SOC9) U1.R18(VDD_SOC10) U1.U10(VDD_DRAM4) U1.U11(VDD_GPU3) U1.U17(VDD_SOC11) U1.U18(VDD_SOC12) U1.V12(VDD_GPU4) U1.W10(VDD_DRAM6) U1.W11(VDD_GPU5) ; also on sheet 12
VDDA_1V8: C99.1 C100.1 C101.1 C104.1 C265.1 C267.1 C400.1 U1.AA14(VDD_ANA0_1P8_2) U1.H13(VDD_MIPI_1P8) U1.H15(VDD_USB_1P8) U1.N19(VDD_24M_XTAL_1P8) U1.N20(VDD_ANA1_1P8_1) U1.P5(VDD_DRAM_PLL_1P8) U1.P19(VDD_ANA1_1P8_2) U1.R19(VDD_ARM_PLL_1P8) U1.Y15(VDD_ANA0_1P8_1) ; also on sheet 12
BOOT_MODE0: R47.1 U1.G26(BOOT_MODE0) ; also on sheet 11
BOOT_MODE1: R79.1 U1.G27(BOOT_MODE1) ; also on sheet 11
BOOT_MODE2: R78.1 U1.C27(BOOT_MODE2) ; also on sheet 11
BOOT_MODE3: R77.1 U1.D26(BOOT_MODE3) ; also on sheet 11
BT_WAKE_DEV: U1.U26(SD1_DATA5) ; also on sheet 10
BT_WAKE_HOST: U1.W27(SD1_DATA6) ; also on sheet 10
CLK_32K_OUT: R100.1 ; also on sheet 12
CLKIN1: TP20.1(Pin1) U1.H27(CLKIN1) ; also on sheet 11
CLKIN2: TP21.1(Pin1) U1.J27(CLKIN2) ; also on sheet 11
CLKOUT1: U1.H26(CLKOUT1) ; also on sheet 11
CLKOUT2: U1.J26(CLKOUT2) ; also on sheet 11
CSI_CKN: U1.A16(MIPI_CSI_CLK_N) ; also on sheet 11
CSI_CKP: U1.B16(MIPI_CSI_CLK_P) ; also on sheet 11
CSI_DN0: U1.A14(MIPI_CSI_D0_N) ; also on sheet 11
CSI_DN1: U1.A15(MIPI_CSI_D1_N) ; also on sheet 11
CSI_DN2: U1.A17(MIPI_CSI_D2_N) ; also on sheet 11
CSI_DN3: U1.A18(MIPI_CSI_D3_N) ; also on sheet 11
CSI_DP0: U1.B14(MIPI_CSI_D0_P) ; also on sheet 11
CSI_DP1: U1.B15(MIPI_CSI_D1_P) ; also on sheet 11
CSI_DP2: U1.B17(MIPI_CSI_D2_P) ; also on sheet 11
CSI_DP3: U1.B18(MIPI_CSI_D3_P) ; also on sheet 11
DRAM_CA0_A: U1.J6(DRAM_AC08/CA0_A_/_A12_/_A12(BC#)) U2.H2(CA0_A)
DRAM_CA1_A: U1.K6(DRAM_AC09/CA1_A_/_A11_/_A11) U2.J2(CA1_A)
DRAM_CA2_A: U1.E4(DRAM_AC10/CA2_A_/_A7_/_A7) U2.H9(CA2_A)
DRAM_CA3_A: U1.D5(DRAM_AC11/CA3_A_/_A8_/_A8) U2.H10(CA3_A)
DRAM_CA4_A: U1.N4(DRAM_AC12/CA4_A_/_A6_/_A6) U2.H11(CA4_A)
DRAM_CA5_A: U1.N5(DRAM_AC13/CA5_A_/_A5_/_A5) U2.J11(CA5_A)
DRAM_CK_C_A: R8.2 U1.L1(DRAM_AC05/CK_c_A_/_BG1_/_A14) U2.J9(CK_c_A)
DRAM_CK_T_A: R8.1 U1.L2(DRAM_AC04/CK_t_A_/_BG0_/_BA2) U2.J8(CK_t_A)
DRAM_CKE0_A: R121.2 U1.F4(DRAM_AC00/CKE0_A_/_CKE0_/_CKE0) U2.J4(CKE0_A)
DRAM_CKE1_A: R158.2 U1.F5(DRAM_AC01/CKE1_A_/_CKE1_/_CKE1) U2.J5(CKE1_A)
DRAM_DMI0: U1.A4(DRAM_DM0) U2.C3(DMI0_A)
DRAM_DMI1: U1.F1(DRAM_DM1) U2.C10(DMI1_A)
DRAM_DQ00: U1.A5(DRAM_DQ00) U2.B2(DQ0_A)
DRAM_DQ01: U1.B5(DRAM_DQ01) U2.C2(DQ1_A)
DRAM_DQ02: U1.D2(DRAM_DQ02) U2.E2(DQ2_A)
DRAM_DQ03: U1.D1(DRAM_DQ03) U2.F2(DQ3_A)
DRAM_DQ04: U1.C1(DRAM_DQ04) U2.F4(DQ4_A)
DRAM_DQ05: U1.B1(DRAM_DQ05) U2.E4(DQ5_A)
DRAM_DQ06: U1.A3(DRAM_DQ06) U2.C4(DQ6_A)
DRAM_DQ07: U1.B4(DRAM_DQ07) U2.B4(DQ7_A)
DRAM_DQ08: U1.F2(DRAM_DQ08) U2.B11(DQ8_A)
DRAM_DQ09: U1.G2(DRAM_DQ09) U2.C11(DQ9_A)
DRAM_DQ10: U1.J1(DRAM_DQ10) U2.E9(DQ13_A)
DRAM_DQ11: U1.J2(DRAM_DQ11) U2.E11(DQ10_A)
DRAM_DQ12: U1.K2(DRAM_DQ12) U2.F11(DQ11_A)
DRAM_DQ13: U1.K1(DRAM_DQ13) U2.F9(DQ12_A)
DRAM_DQ14: U1.E1(DRAM_DQ14) U2.B9(DQ15_A)
DRAM_DQ15: U1.E2(DRAM_DQ15) U2.C9(DQ14_A)
DRAM_nCS0_A: U1.K4(DRAM_AC02/CS0_A_/_CS0_n_/_CS0#) U2.H4(CS0_A)
DRAM_nCS1_A: U1.J4(DRAM_AC03/CS1_A_/_C0_/_--) U2.H3(CS1_A)
DRAM_nRESET: R4.2 R204.2 U1.R1(DRAM_RESET_N) U2.T11(~{RESET})
DRAM_SDQS0_C: U1.B2(DRAM_DQS0_N) U2.E3(DQS0_c_A)
DRAM_SDQS0_T: U1.A2(DRAM_DQS0_P) U2.D3(DQS0_t_A)
DRAM_SDQS1_C: U1.H1(DRAM_DQS1_N) U2.E10(DQS1_c_A)
DRAM_SDQS1_T: U1.G1(DRAM_DQS1_P) U2.D10(DQS1_t_A)
DRAM_ZQ0: R5.2 U2.A5(ZQ0)
DRAM_ZQ1: R157.2 U2.A8(ZQ1)
DSI_CKN: U1.A11(MIPI_DSI_CLK_N) ; also on sheet 11
DSI_CKP: U1.B11(MIPI_DSI_CLK_P) ; also on sheet 11
DSI_DN0: U1.A9(MIPI_DSI_D0_N) ; also on sheet 11
DSI_DN1: U1.A10(MIPI_DSI_D1_N) ; also on sheet 11
DSI_DN2: U1.A12(MIPI_DSI_D2_N) ; also on sheet 11
DSI_DN3: U1.A13(MIPI_DSI_D3_N) ; also on sheet 11
DSI_DP0: U1.B9(MIPI_DSI_D0_P) ; also on sheet 11
DSI_DP1: U1.B10(MIPI_DSI_D1_P) ; also on sheet 11
DSI_DP2: U1.B12(MIPI_DSI_D2_P) ; also on sheet 11
DSI_DP3: U1.B13(MIPI_DSI_D3_P) ; also on sheet 11
ECSPI2_MISO: U1.A8(ECSPI2_MISO) ; also on sheet 11
ECSPI2_MOSI: U1.B8(ECSPI2_MOSI) ; also on sheet 11
ECSPI2_SCLK: U1.E6(ECSPI2_SCLK) ; also on sheet 11
ECSPI2_SS0: U1.A6(ECSPI2_SS0) ; also on sheet 11
ENET_MDC: U1.AC27(ENET_MDC) ; also on sheet 11
ENET_MDIO: U1.AB27(ENET_MDIO) ; also on sheet 11
ENET_RD0: U1.AE27(ENET_RD0) ; also on sheet 11
ENET_RD1: U1.AD27(ENET_RD1) ; also on sheet 11
ENET_RD2: U1.AD26(ENET_RD2) ; also on sheet 11
ENET_RD3: U1.AC26(ENET_RD3) ; also on sheet 11
ENET_RX_CTL: U1.AF27(ENET_RX_CTL) ; also on sheet 11
ENET_RXC: U1.AE26(ENET_RXC) ; also on sheet 11
ENET_TD0: U1.AG26(ENET_TD0) ; also on sheet 11
ENET_TD1: U1.AF26(ENET_TD1) ; also on sheet 11
ENET_TD2: U1.AG25(ENET_TD2) ; also on sheet 11
ENET_TD3: U1.AF25(ENET_TD3) ; also on sheet 11
ENET_TX_CTL: U1.AF24(ENET_TX_CTL) ; also on sheet 11
ENET_TXC: U1.AG24(ENET_TXC) ; also on sheet 11
GPIO1_IO01: U1.AF14(GPIO1_IO01) ; also on sheet 11
GPIO1_IO05: U1.AF12(GPIO1_IO05) ; also on sheet 11
GPIO1_IO06: U1.AG11(GPIO1_IO06) ; also on sheet 11
GPIO1_IO07: U1.AF11(GPIO1_IO07) ; also on sheet 11
GPIO1_IO08: U1.AG10(GPIO1_IO08) ; also on sheet 11
GPIO1_IO09: U1.AF10(GPIO1_IO09) ; also on sheet 11
GPIO1_IO10: U1.AD10(GPIO1_IO10) ; also on sheet 11
GPIO1_IO11: U1.AC10(GPIO1_IO11) ; also on sheet 11
GPIO1_IO12: U1.AB10(GPIO1_IO12) ; also on sheet 11
GPIO1_IO13: U1.AD9(GPIO1_IO13) ; also on sheet 11
GPIO1_IO14: U1.AC9(GPIO1_IO14) ; also on sheet 11
GPIO1_IO15: U1.AB9(GPIO1_IO15) ; also on sheet 11
I2C1_SCL: R10.2 U1.E9(I2C1_SCL) ; also on sheet 12
I2C1_SDA: R11.2 U1.F9(I2C1_SDA) ; also on sheet 12
I2C2_SCL: R12.2 U1.D10(I2C2_SCL) ; also on sheet 11
I2C2_SDA: R13.2 U1.D9(I2C2_SDA) ; also on sheet 11
I2C3_SCL: R14.2 U1.E10(I2C3_SCL) ; also on sheet 11
I2C3_SDA: R15.2 U1.F10(I2C3_SDA) ; also on sheet 11
I2C4_SCL: R16.2 U1.D13(I2C4_SCL) ; also on sheet 11
I2C4_SDA: R17.2 U1.E13(I2C4_SDA) ; also on sheet 11
JTAG_MOD: R23.1 U1.D27(JTAG_MOD)
JTAG_TCK: R18.1 TP4.1(Pin1) U1.F26(JTAG_TCK) ; also on sheet 11
JTAG_TDI: TP2.1(Pin1) U1.E27(JTAG_TDI) ; also on sheet 11
JTAG_TDO: TP5.1(Pin1) U1.E26(JTAG_TDO) ; also on sheet 11
JTAG_TMS: R27.2 TP3.1(Pin1) ; also on sheet 11
JTAG_TMS_R: R27.1 U1.F27(JTAG_TMS)
NVCC_1V8: C3.1 C5.1 C21.1 C23.1 C105.1 C106.1 C108.1 C109.1 C241.1 C266.1 C370.1 C371.1 C372.1 C384.1 R10.1 R11.1 R12.1 R13.1 R14.1 R15.1 R16.1 R17.1 R47.2 R77.2 R78.2 R79.2 U1.AB13(PVCC0_1P8) U1.J11(NVCC_I2C) U1.J12(NVCC_UART) U1.J13(PVCC2_1P8) U1.L19(NVCC_JTAG) U1.M19(NVCC_CLK) U1.T19(PVCC1_1P8) U1.U19(NVCC_NAND) U1.V19(NVCC_SAI2) U1.V20(NVCC_SD1) U1.W12(NVCC_GPIO1) U2.F1(VDD1_1) U2.F12(VDD1_2) U2.G4(VDD1_3) U2.G9(VDD1_4) U2.T4(VDD1_5) U2.T9(VDD1_6) U2.U1(VDD1_7) U2.U12(VDD1_8) ; also on sheet 10 11 12 13
NVCC_3V3: C6.1 C8.1 C30.1 C260.1 C264.1 R125.1 U1.H10(NVCC_ECSPI) U1.K19(VDD_USB_3P3) U1.W17(NVCC_SAI5) U1.Y10(NVCC_SAI3) ; also on sheet 10 11 12 13
NVCC_DRAM_1V1: C88.1 C89.1 C90.1 C91.1 C92.1 C93.1 C94.1 C95.1 C110.1 C111.1 C112.1 C113.1 C114.1 C115.1 C117.1 C118.1 C119.1 C373.1 C374.1 C375.1 C376.1 C378.1 C379.1 C380.1 C381.1 C382.1 R5.1 R157.1 U1.K8(NVCC_DRAM1) U1.K9(NVCC_DRAM2) U1.L9(NVCC_DRAM3) U1.M9(NVCC_DRAM4) U1.N8(NVCC_DRAM5) U1.N9(NVCC_DRAM6) U1.P7(NVCC_DRAM13) U1.R8(NVCC_DRAM7) U1.R9(NVCC_DRAM8) U1.T9(NVCC_DRAM9) U1.U9(NVCC_DRAM10) U1.V8(NVCC_DRAM11) U1.V9(NVCC_DRAM12) U2.A4(VDD2_1) U2.A9(VDD2_2) U2.AA3(VDDQ17) U2.AA5(VDDQ18) U2.AA8(VDDQ19) U2.AA10(VDDQ20) U2.AB4(VDD2_23) U2.AB9(VDD2_24) U2.B3(VDDQ1) U2.B5(VDDQ2) U2.B8(VDDQ3) U2.B10(VDDQ4) U2.D1(VDDQ5) U2.D5(VDDQ6) U2.D8(VDDQ7) U2.D12(VDDQ8) U2.F3(VDDQ9) U2.F5(VDD2_3) U2.F8(VDD2_4) U2.F10(VDDQ10) U2.G2(ODT(ca)_A) U2.H1(VDD2_5) U2.H5(VDD2_6) U2.H8(VDD2_7) U2.H12(VDD2_8) U2.K1(VDD2_9) U2.K3(VDD2_10) U2.K10(VDD2_11) U2.K12(VDD2_12) U2.N1(VDD2_13) U2.N3(VDD2_14) U2.N10(VDD2_15) U2.N12(VDD2_16) U2.R1(VDD2_17) U2.R5(VDD2_18) U2.R8(VDD2_19) U2.R12(VDD2_20) U2.U3(VDDQ11) U2.U5(VDD2_21) U2.U8(VDD2_22) U2.U10(VDDQ12) U2.W1(VDDQ13) U2.W5(VDDQ14) U2.W8(VDDQ15) U2.W12(VDDQ16) ; also on sheet 12
NVCC_ENET: C392.1 U1.W22(NVCC_ENET) ; also on sheet 11
NVCC_SD2: C17.1 R119.1 R120.1 R133.1 U1.V22(NVCC_SD2) ; also on sheet 12
NVCC_SNVS_1V8: C391.1 R20.1 R21.1 R102.1 U1.J22(NVCC_SNVS_1P8) ; also on sheet 12
ONOFF: R21.2 TP7.1(TP) U1.A25(ONOFF) ; also on sheet 11
PDM_CLK: U1.AC15(SAI5_RXC) ; also on sheet 11
PDM_DATA0: U1.AD18(SAI5_RXD0) ; also on sheet 11
PDM_DATA1: U1.AC14(SAI5_RXD1) ; also on sheet 11
PDM_DATA2: U1.AD13(SAI5_RXD2) ; also on sheet 11
PDM_DATA3: U1.AC13(SAI5_RXD3) ; also on sheet 11
PHY_VREF: TP58.1(Pin1) U1.P1(DRAM_VREF)
PMIC_nINT: U1.AF13(GPIO1_IO03) ; also on sheet 12
PMIC_ON_REQ: TP6.1(TP) U1.A24(PMIC_ON_REQ) ; also on sheet 11 12
PMIC_STBY_REQ: TP10.1(TP) U1.E24(PMIC_STBY_REQ) ; also on sheet 12
POR_B: R20.2 TP9.1(TP) U1.B24(POR_B) ; also on sheet 11 12
QSPIA_DATA0: U1.P23(NAND_DATA00) ; also on sheet 13
QSPIA_DATA1: U1.K24(NAND_DATA01) ; also on sheet 13
QSPIA_DATA2: U1.K23(NAND_DATA02) ; also on sheet 13
QSPIA_DATA3: U1.N23(NAND_DATA03) ; also on sheet 13
QSPIA_nSS0: U1.N24(NAND_CE0_B) ; also on sheet 13
QSPIA_SCLK: U1.N22(NAND_ALE) ; also on sheet 13
REF_CLK_32K: U1.AG14(GPIO1_IO00) ; also on sheet 10 11
REG_PD_B: U1.R23(SD1_RESET_B) ; also on sheet 10
RTC_RESET_B: R102.2 TP8.1(TP) U1.F24(RTC_RESET_B) ; also on sheet 12
SAI2_MCLK: U1.AD19(SAI2_MCLK) ; also on sheet 11
SAI2_RXC: U1.AB22(SAI2_RXC) ; also on sheet 11
SAI2_RXD: U1.AC24(SAI2_RXD0) ; also on sheet 10
SAI2_RXFS: U1.AC19(SAI2_RXFS) ; also on sheet 11
SAI2_TXC: U1.AD22(SAI2_TXC) ; also on sheet 10 12
SAI2_TXD: U1.AC22(SAI2_TXD0) ; also on sheet 10 12
SAI2_TXFS: U1.AD23(SAI2_TXFS) ; also on sheet 10
SAI3_MCLK: U1.AD6(SAI3_MCLK) ; also on sheet 11
SAI3_RXC: U1.AG7(SAI3_RXC) ; also on sheet 11
SAI3_RXD: U1.AF7(SAI3_RXD) ; also on sheet 11
SAI3_RXFS: U1.AG8(SAI3_RXFS) ; also on sheet 11
SAI3_TXC: U1.AG6(SAI3_TXC) ; also on sheet 11
SAI3_TXD: U1.AF6(SAI3_TXD) ; also on sheet 11
SAI3_TXFS: U1.AC6(SAI3_TXFS) ; also on sheet 11
SAI5_MCLK: U1.AD15(SAI5_MCLK) ; also on sheet 11
SAI5_RXFS: U1.AB15(SAI5_RXFS) ; also on sheet 11
SD1_CLK: U1.V26(SD1_CLK) ; also on sheet 10
SD1_CMD: U1.V27(SD1_CMD) ; also on sheet 10
SD1_DATA0: U1.Y27(SD1_DATA0) ; also on sheet 10
SD1_DATA1: U1.Y26(SD1_DATA1) ; also on sheet 10
SD1_DATA2: U1.T27(SD1_DATA2) ; also on sheet 10
SD1_DATA3: U1.T26(SD1_DATA3) ; also on sheet 10
SD1_STROBE: U1.R24(SD1_STROBE) ; also on sheet 11
SD2_CLK: U1.W23(SD2_CLK) ; also on sheet 11
SD2_CMD: R120.2 U1.W24(SD2_CMD) ; also on sheet 11
SD2_DATA0: R119.2 U1.AB23(SD2_DATA0) ; also on sheet 11
SD2_DATA1: U1.AB24(SD2_DATA1) ; also on sheet 11
SD2_DATA2: U1.V24(SD2_DATA2) ; also on sheet 11
SD2_DATA3: U1.V23(SD2_DATA3) ; also on sheet 11
SD2_nCD: U1.AA26(SD2_CD_B) ; also on sheet 11
SD2_nRST: R133.2 U1.AB26(SD2_RESET_B) ; also on sheet 11
SD2_VSEL: U1.AG12(GPIO1_IO04) ; also on sheet 12
SD2_WP: U1.AA27(SD2_WP) ; also on sheet 11
SD3_CLK: U1.R26(NAND_WE_B) ; also on sheet 13
SD3_CMD: U1.R27(NAND_WP_B) ; also on sheet 13
SD3_DATA0: U1.M26(NAND_DATA04) ; also on sheet 13
SD3_DATA1: U1.L26(NAND_DATA05) ; also on sheet 13
SD3_DATA2: U1.K26(NAND_DATA06) ; also on sheet 13
SD3_DATA3: U1.N26(NAND_DATA07) ; also on sheet 13
SD3_DATA4: U1.N27(NAND_RE_B) ; also on sheet 13
SD3_DATA5: U1.M27(NAND_CE2_B) ; also on sheet 13
SD3_DATA6: U1.L27(NAND_CE3_B) ; also on sheet 13
SD3_DATA7: U1.K27(NAND_CLE) ; also on sheet 13
SD3_STROBE: U1.P27(NAND_CE1_B) ; also on sheet 13
SPDIF_EXT_CLK: U1.AF8(SPDIF_EXT_CLK) ; also on sheet 11
SPDIF_RX: U1.AG9(SPDIF_RX) ; also on sheet 11
SPDIF_TX: U1.AF9(SPDIF_TX) ; also on sheet 11
SYS_STATUS: Q1.1(GATE) U1.P26(NAND_READY_B)
TS_RES_EXT: R103.1 U1.J24(TSENSOR_RES_EXT)
TS_TEST_OUT: TP19.1(Pin1) U1.J23(TSENSOR_TEST_OUT)
UART1_CTS: U1.E18(UART3_RXD) ; also on sheet 10
UART1_RTS: U1.D18(UART3_TXD) ; also on sheet 10
UART1_RXD: U1.E14(UART1_RXD) ; also on sheet 10
UART1_TXD: U1.F13(UART1_TXD) ; also on sheet 10
UART2_RXD: U1.F15(UART2_RXD) ; also on sheet 11
UART2_TXD: U1.E15(UART2_TXD) ; also on sheet 11
UART3_CTS: U1.A7(ECSPI1_MISO) ; also on sheet 11
UART3_RTS: U1.B6(ECSPI1_SS0) ; also on sheet 11
UART3_RXD: U1.D6(ECSPI1_SCLK) ; also on sheet 11
UART3_TXD: U1.B7(ECSPI1_MOSI) ; also on sheet 11
UART4_RXD: U1.F19(UART4_RXD) ; also on sheet 11
UART4_TXD: U1.F18(UART4_TXD) ; also on sheet 11
USB1_DN: U1.A22(USB1_DN) ; also on sheet 11
USB1_DP: U1.B22(USB1_DP) ; also on sheet 11
USB1_ID: U1.D22(USB1_ID) ; also on sheet 11
USB1_VBUS: C393.1 R108.2 ; also on sheet 11
WDOG_B: U1.AG13(GPIO1_IO02) ; also on sheet 12
WL_WAKE_DEV: U1.U27(SD1_DATA4) ; also on sheet 10
WL_WAKE_HOST: U1.W26(SD1_DATA7) ; also on sheet 10
XTALI_24M: C123.1 R26.1 TP38.1(Pin1) U1.B27(24M_XTALI) Y1.3
XTALI_32K: R100.2 TP39.1(Pin1) U1.A26(RTC_XTALI)
XTALO_24M: C124.1 R26.2 U1.C26(24M_XTALO) Y1.1
XTALO_32K: R113.2 U1.B25(RTC_XTALO)
N102271152: R7.2 U1.P2(DRAM_ZN)
N106370682: R108.1 U1.F22(USB1_VBUS)
N106370752: R29.1 U1.E19(USB1_TXRTUNE)
N107005929: TP15.1(Pin1) U1.N2(DRAM_AC19/MTEST_/_MTEST_/_MTEST)
N108250870: C268.1 U1.D15(MIPI_VREG_CAP)
N109477029: D1.C(CATHODE) Q1.3(DRAIN)
N109477483: C245.1 U1.R22(NAND_DQS)
N109586960: R204.1 U2.G11(NC1)
N109728292: D1.A(ANODE) R125.2

Not connected (* = marked no-connect by the designer): U1 A19(NC)* A20(NC)* A21(NC)* A23(NC)* AA1(NC)* AA2(NC)* AB1(NC)* AB2(NC)* AB4(DRAM_AC20/CKE0_B_/_CK_t_B_/_CK_B)* AB5(DRAM_AC21/CKE1_B_/_CK_c_B_/_CK#_B)* AB6(DRAM_AC38/--_/_CS1_n_/_CS1#)* AB18(NC)* AB19(NC)* AC1(NC)* AC2(NC)* AC4(DRAM_AC30/CA2_B_/_A10(AP)_/_A10(AP))* AC18(NC)* AD1(NC)* AD2(NC)* AD5(DRAM_AC31/CA3_B_/_A0_/_A0)* AE1(NC)* AF1(NC)* AF2(NC)* AF4(NC)* AF5(NC)* AF15(NC)* AF16(NC)* AF17(NC)* AF18(NC)* AF19(NC)* AF20(NC)* AF21(NC)* AF22(NC)* AF23(NC)* AG2(NC)* AG3(NC)* AG4(NC)* AG5(NC)* AG15(NC)* AG16(NC)* AG17(NC)* AG18(NC)* AG19(NC)* AG20(NC)* AG21(NC)* AG22(NC)* AG23(NC)* B19(NC)* B20(NC)* B21(NC)* B23(NC)* D19(NC)* D23(NC)* E22(NC)* F6(DRAM_AC06/--_/_ACT_n_/_A15)* F23(NC)* G14(NC)* J5(DRAM_AC07/--_/_A9_/_A9)* J16(NC)* J18(NC)* K5(DRAM_AC14/_--_/_A4_/_A4)* K12(NC)* K13(NC)* L11(NC)* L13(NC)* M1(DRAM_AC16/--_/_CK_t_A_/_CK_A)* M2(DRAM_AC17/--_/_CK_c_A_/_CK#_A)* M13(NC)* M14(NC)* N1(DRAM_AC26/--_/_BA1_/_BA1)* N6(DRAM_AC15/--_/_A3_/_A3)* N11(NC)* R2(DRAM_ALERT_N)* R4(DRAM_AC32/CA4_B_/_C2_/_--)* R5(DRAM_AC33/CA5_B/CAS_n(A15)/CAS#)* R6(DRAM_AC27/--_/_PARITY_/_--)* T1(DRAM_AC34/_--_/WE_n(A14)/WE#)* T2(DRAM_AC35/--_/_RAS_n(A16)_/_RAS#)* U1(DRAM_AC25/CK_c_B_/_A1_/_A1)* U2(DRAM_AC24/CK_t_B_/_A2_/_A2)* V1(NC)* V2(NC)* V4(DRAM_AC23/CS0_B_/_--_/_--)* V5(DRAM_AC36/--_/_ODT0_/_ODT0)* V6(DRAM_AC29/CA1_B_/_BA0_/_BA0)* W1(NC)* W2(NC)* W4(DRAM_AC22/CS1_B_/_--_/_--)* W5(DRAM_AC37/--_/_ODT1_/_ODT1)* W6(DRAM_AC28/CA0_B_/_A13_/_A13)* W18(NC)* Y1(NC)*; U2 A1(DNU1)* A2(DNU2)* A11(DNU3)* A12(DNU4)* AA1(DNU7)* AA2(NC37)* AA4(NC38)* AA9(NC39)* AA11(NC40)* AA12(DNU8)* AB1(DNU9)* AB2(DNU10)* AB11(DNU11)* AB12(DNU12)* B1(DNU5)* B12(DNU6)* K5(NC2)* K8(NC3)* N5(NC4)* N8(NC5)* P2(NC6)* P4(NC7)* P5(NC8)* P8(NC9)* P9(NC10)* P11(NC11)* R2(NC12)* R3(NC13)* R4(NC14)* R9(NC15)* R10(NC16)* R11(NC17)* T2(NC18)* U2(NC19)* U4(NC20)* U9(NC21)* U11(NC22)* V2(NC23)* V3(NC24)* V4(NC25)* V9(NC26)* V10(NC27)* V11(NC28)* W3(NC29)* W10(NC30)* Y2(NC31)* Y3(NC32)* Y4(NC33)* Y9(NC34)* Y10(NC35)* Y11(NC36)*

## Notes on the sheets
sheet 1
- Boot Mode
- i.MX8M Nano Boot Mode
- BOOT_PIN[3]
- BOOT_PIN[2]
- BOOT_PIN[1]
- BOOT_PIN[0]
- Boot Modes
- BOOT_MODE3
  (TEST_MODE)
- BOOT_MODE2
  (JTAG_TRST_B)
- BOOT_MODE1
- BOOT_MODE0
- Function
- 0
- 0
- 0
- 0
- Boot From Internal Fuses
- 0
- 0
- 0
- 1
- USB Serial Download
- 0
- 1
- 0
- USDHC3 (eMMC boot only, SD3 8-bit)
- 0
- 0
- 0
- 1
- 1
- USDHC2 (SD boot only, SD2)
- 0
- 1
- 0
- 0
- NAND 8-bit single device 256 page
- 0
- 1
- 0
- 1
- NAND 8-bit single device 512 page
- 0
- 1
- 1
- 0
- QSPI 3B Read
- 0
- 1
- 1
- 1
- QSPI Hyperflash 3.3V
- 1
- 0
- 0
- 0
- ecSPI Boot
- Note:
- 1
- 0
- 0
- 1
- Reserved
- 1. BOOT_MODE0-3 singals are used for boot selections
- 2. BOOT_MODE singals have internal PD before and after POR_B reset is deasserted!
- 1
- 0
- 1
- 0
- Reserved
- 3. When using Base Board for Multi boot selection, you must keep the resistors DNP on SOM board!
- 1
- 0
- 1
- 1
- Reserved
- Reserved
  (Boot on I2C connected to BOOT PIN[3:2])
- 1
- 1
- 0
- 0
- 1
- 1
- 0
- 1
- Reserved
- 1
- 1
- 1
- 0
- Infinite Loop Mode
- 1
- 1
- 1
- 1
- Test Mode
sheet 2
- 8MNANOLPD4-CPU
- (i.MX8M Nano Reference Board)
- Table of Content
- Revision History
- Page 1
- Cover
- Rev. Code
- Date
- By
- Description
- Page 2
- Block Diagram
- A
- 2020-01-07
- Mac
- Initial version release
- Page 3
- PWR TREE
- A1
- 2020-05-09
- Vector
- DNP C285,C287
- Page 4
- CPU PWR
- Page 5
- LPDDR4
- Page 6
- CPU IO
- Page 7
- CPU PHY
- Page 8
- CPU MISC
- Page 9
- eMMC/QSPI
- Page 10
- WIFI/BT Module
- Page 11
- BOOT CFG
- Page 12
- PMIC PCA9450B
- Page 13
- SOM Interface
- 1. Interrupted lines coded with the same letter or letter
      combinations are electrically connected.
- 2. Device type number is for reference only. The number
      varies with the manufacturer.
- 3. Special signal usage:
- _B Denotes - Active-Low Signal
- <> or [] Denotes - Vectored Signals
- 4. Interpret diagram in accordance with American
  National Standards Institute specifications, current
  revision, with the exception of logic block symbology.
- Preliminary - Subject to Change without Notice!
- This board was designed for maximum flexibility in
  software  development and demonstrates multiple
  functions possible with i.MX processors. Although best
  design practices have been applied, some areas may
  not be suitable for a mass-production design.
- NXP CONFIDENTIAL AND PROPRIETARY
sheet 3
- 8MNANOLPD4-EVK Block Diagram
- MIPI DSI
- MIPI CSI
- JTAG
- Infrared
     / LED
- mini-SAS CN
- mini-SAS CN
- 10 PIN Header
- LANE x4
- LANE x4
- JTAG
- GPIO/PWM
- MIPI DSI
- MIPI CSI
- JTAG
- PWM
- QSPI Nor
- USB 2.0 OTG
- USB TYPE-C
- USB OTG
- x4 bits
- Micron 32MB
  MT25QU256ABA1
- QSPIA
- DRP x1
- Button
- PMIC
- WiFi/BT
- 2.4/5GHz
- POWER
- SDHC1/UART/PCM
- Reset
- NXP PCA9450B
- 802.11a/b/g/n/ac
- N
- X
- P
- LPDDR4
   DRAM
- DAC
- x16 bits
- I2S
- DRAM
- SAI
- Kingston LPDDR4 16Gb
- Cirrus Logic WM8524
- i.MX8M Nano
- C1612PC2WDGTKR-U
- ARM CORTEX 4x A53 + M7
- eMMC 5.1
- x8 bits
- Sandisk 32GB
  SDINBDG4-32G-I1
- SDHC3
- Giga Ethernet
- RGMII
- RJ45
- RGMII
- Qualcomm: AR8031
- MicroSD
- x4 bits
- SDHC2
- SD3.0 Support
- DBG UART
- Button
- UART
- ONOFF/GPIO
- x2 UART(A53/M7)
- ONOFF
- UART->USB FT2232D
- GPIO/UART
- SAI/I2C
- I2C
- GPIO/UART...
- GPIO/SAI/I2C...
- I2C
- EXP CN
- Audio Card
- I2C CN
- On SOM Board
- GPIO/UART
- SAI/GPIO/I2C...
- I2C/RST
sheet 4
- 8MNANOLPD4-EVK PWR TREE
- PMIC: PCA9450B
- CPU: i.MX8M Nano
- SEQ
- REG
- TYP
- Max Capability(mA)
- SEQ
- PWR/Signal
- TYP
- Required(mA)
- 1
  2
  3
  4
  5
  6
  6
  7
  8
  9
  9
  10
  11
- LDO1
  LDO2
  RTC_RESET_B
  RTC_CLK
  BUCK1
  BUCK2
  LDO3
  BUCK5
  BUCK6
  BUCK4
  LDO5
  POR_B
  LDO4
- 1.8
  0.85
  --
  --
  0.85/0.95
  0.85/0.95/1.0
  1.8
  1.8
  1.1
  3.3
  3.3/1.8
  --
  1.2
- 10
  10
  --
  --
  3000
  3000
  300
  2000
  2000
  3000
  150
  --
  200
- 1
  2
  3
  4
  5
  6
  6
  7
  8
  9
  9
  10
  11
- NVCC_SNVS_1V8
  VDD_SNVS_0V8
  RTC_RESET_B
  CLK_32K_OUT
  VDD_SOC&DRAM&PU_0V9
  VDD_ARM_0V9
  VDDA_1V8
  VDD_1V8/NVCC_1V8
  NVCC_DRAM_1V1
  VDD_3V3/NVCC_3V3
  NVCC_SD2
  POR_B
  VDD_PHY_1V2
  NVCC_ENET
- 1.8
  0.8
  --
  --
  0.85/0.95
  0.85/0.95/1.0
  1.8
  1.8
  1.1
  3.3
  3.3/1.8
  --
  1.2
  1.8/2.5
- 10
  10
  --
  --
  2600
  2200
  300
  500
  NxCxVx(0.5xF)
  NxCxVx(0.5xF)
  100
  --
  10
  10
- VSYS
- 5V
- Base Board
- NVCC_ENET
- LPDDR4
- VDD1
  VDD2/VDDQ
- QSPI
- VCC
- eMMC
- VCCQ
  VCC
- WiFi/BT
- VBAT
  VIO
- Power SW
- ADP191ACBZ-R7
- Base Board
  Peripherals
sheet 5
- i.MX8M Nano PWR
- PMIC Sense point
- Supply from Base Board
- PMIC Sense point
sheet 6
- LPDDR4 2GB
- Power supply voltage ramp:
  RESET_n is held LOW.
  VDD1 >= VDD2
  VDD2 >= VDDQ
- 1.06-1.14V
- VREF internally generated
- Data Bus
- Command/Address
- Pin Name
- LPDDR4
- DDR4
- Pin Name
- LPDDR4
- DDR4
- DRAM_DQS0_P
  DRAM_DQS0_N
  DRAM_DM0
  DRAM_DQ00
  DRAM_DQ01
  DRAM_DQ02
  DRAM_DQ03
  DRAM_DQ04
  DRAM_DQ05
  DRAM_DQ06
  DRAM_DQ07
  DRAM_DQS1_P
  DRAM_DQS1_N
  DRAM_DM1
  DRAM_DQ08
  DRAM_DQ09
  DRAM_DQ10
  DRAM_DQ11
  DRAM_DQ12
  DRAM_DQ13
  DRAM_DQ14
  DRAM_DQ15
  DRAM_DQS2_P
  DRAM_DQS2_N
  DRAM_DM2
  DRAM_DQ16
  DRAM_DQ17
  DRAM_DQ18
  DRAM_DQ19
  DRAM_DQ20
  DRAM_DQ21
  DRAM_DQ22
  DRAM_DQ23
  DRAM_DQS3_P
  DRAM_DQS3_N
  DRAM_DM3
  DRAM_DQ24
  DRAM_DQ25
  DRAM_DQ26
  DRAM_DQ27
  DRAM_DQ28
  DRAM_DQ29
  DRAM_DQ30
  DRAM_DQ31
- DQS0_t_A
  DQS0_c_A
  DMI0_A
  DQ0_A
  DQ1_A
  DQ2_A
  DQ3_A
  DQ4_A
  DQ5_A
  DQ6_A
  DQ7_A
  DQS1_t_A
  DQS1_c_A
  DMI1_A
  DQ08_A
  DQ09_A
  DQ10_A
  DQ11_A
  DQ12_A
  DQ13_A
  DQ14_A
  DQ15_A
  DQS0_t_B
  DQS0_c_B
  DMI0_B
  DQ0_B
  DQ1_B
  DQ2_B
  DQ3_B
  DQ4_B
  DQ5_B
  DQ6_B
  DQ7_B
  DQS1_t_B
  DQS1_c_B
  DMI1_B
  DQ08_B
  DQ09_B
  DQ10_B
  DQ11_B
  DQ12_B
  DQ13_B
  DQ14_B
  DQ15_B
- DQSL_t_A
  DQSL_c_A
  DML_n_A / DBIL_n_A
  DQL0_A
  DQL1_A
  DQL2_A
  DQL3_A
  DQL4_A
  DQL5_A
  DQL6_A
  DQL7_A
  DQSU_t_A
  DQSU_c_A
  DMU_n_A / DBIU_n_A
  DQU0_A
  DQU1_A
  DQU2_A
  DQU3_A
  DQU4_A
  DQU5_A
  DQU6_A
  DQU7_A
  DQSL_t_B
  DQSL_c_B
  DML_n_B / DBIL_n_B
  DQL0_B
  DQL1_B
  DQL2_B
  DQL3_B
  DQL4_B
  DQL5_B
  DQL6_B
  DQL7_B
  DQSU_t_B
  DQSU_c_B
  DMU_n_B / DBIU_n_B
  DQU0_B
  DQU1_B
  DQU2_B
  DQU3_B
  DQU4_B
  DQU5_B
  DQU6_B
  DQU7_B
- DRAM_RESET_N
  DRAM_ALERT_N
  DRAM_AC00
  DRAM_AC01
  DRAM_AC02
  DRAM_AC03
  DRAM_AC04
  DRAM_AC05
  DRAM_AC06
  DRAM_AC07
  DRAM_AC08
  DRAM_AC09
  DRAM_AC10
  DRAM_AC11
  DRAM_AC12
  DRAM_AC13
  DRAM_AC14
  DRAM_AC15
  DRAM_AC16
  DRAM_AC17
  DRAM_AC19
  DRAM_AC20
  DRAM_AC21
  DRAM_AC22
  DRAM_AC23
  DRAM_AC24
  DRAM_AC25
  DRAM_AC26
  DRAM_AC27
  DRAM_AC28
  DRAM_AC29
  DRAM_AC30
  DRAM_AC31
  DRAM_AC32
  DRAM_AC33
  DRAM_AC34
  DRAM_AC35
  DRAM_AC36
  DRAM_AC37
  DRAM_AC38
  DRAM_ZN
  DRAM_VREF
- RESET_N
  MTEST1
  CKE0_A
  CKE1_A
  CS0_A
  CS1_A
  CK_t_A
  CK_c_A
  /
  /
  CA0_A
  CA1_A
  CA2_A
  CA3_A
  CA4_A
  CA5_A
  /
  /
  /
  MTEST
  CKE0_B
  CKE1_B
  CS1_B
  CS0_B
  CK_t_B
  CK_c_B
  /
  /
  CA0_B
  CA1_B
  CA2_B
  CA3_B
  CA4_B
  CA5_B
  /
  /
  /
  /
  ZQ
  VREF
- RESET_n
  ALERT_n / MTEST1
  CKE0
  CKE1
  CS0_n
  C0
  BG0
  BG1
  ACT_n
  A9
  A12
  A11
  A7
  A8
  A6
  A5
  A4
  A3
  CK_t_A
  CK_c_A
  MTEST
  CK_t_B
  CK_c_B
  /
  /
  A2
  A1
  BA1
  PARITY
  A13
  BA0
  A10 / AP
  A0
  C2
  CAS_n / A15
  WE_n / A14
  RAS_n / A16
  ODT0
  ODT1
  CS1_n
  ZQ
  VREF
sheet 7
- i.MX8M Nano IO Interface
- Dummy DQS for QSPI High Speed Timing
- On Board BT
- Configure internal pull up at CPU side, open drain output
- Configure internal pull up at CPU side
- Note:
- GPIO1_IO02 is the only pin can be used as WDOG_B to
  toggle the PMIC.
  When entering boundary-scan mode, this pin is set to low by
  the processor.
  The PMIC PCA9450 default disables WDOG_B Reset and
  the cold reset event is generated by WDOG_B falling edge,
  so the WDOG_B is always low that will not impact to enter
  boundary scan mode.
- LED
- On Board WiFi
- Configure internal pull up at CPU side
- Configure internal pull up at CPU side
- Blink:  SYS_STATUS
- External PU R133 is necessary for SD2 power control!
- On Board BT
- A53 Debug
- On Board BT
- M7 Debug
sheet 8
- i.MX8M Nano MISC
- JTAG Debug
- # System On/Off Button
- PU
- PD
- Factory use only
- Recommend to use external clock source,
  XTALO must be connected to NVCC_SNVS_1V8/2, or VDD_SNVS_0V8!
- Refer to datasheet
sheet 9
- i.MX8M Nano PHYs
- Voltage Range:0~3.3V
